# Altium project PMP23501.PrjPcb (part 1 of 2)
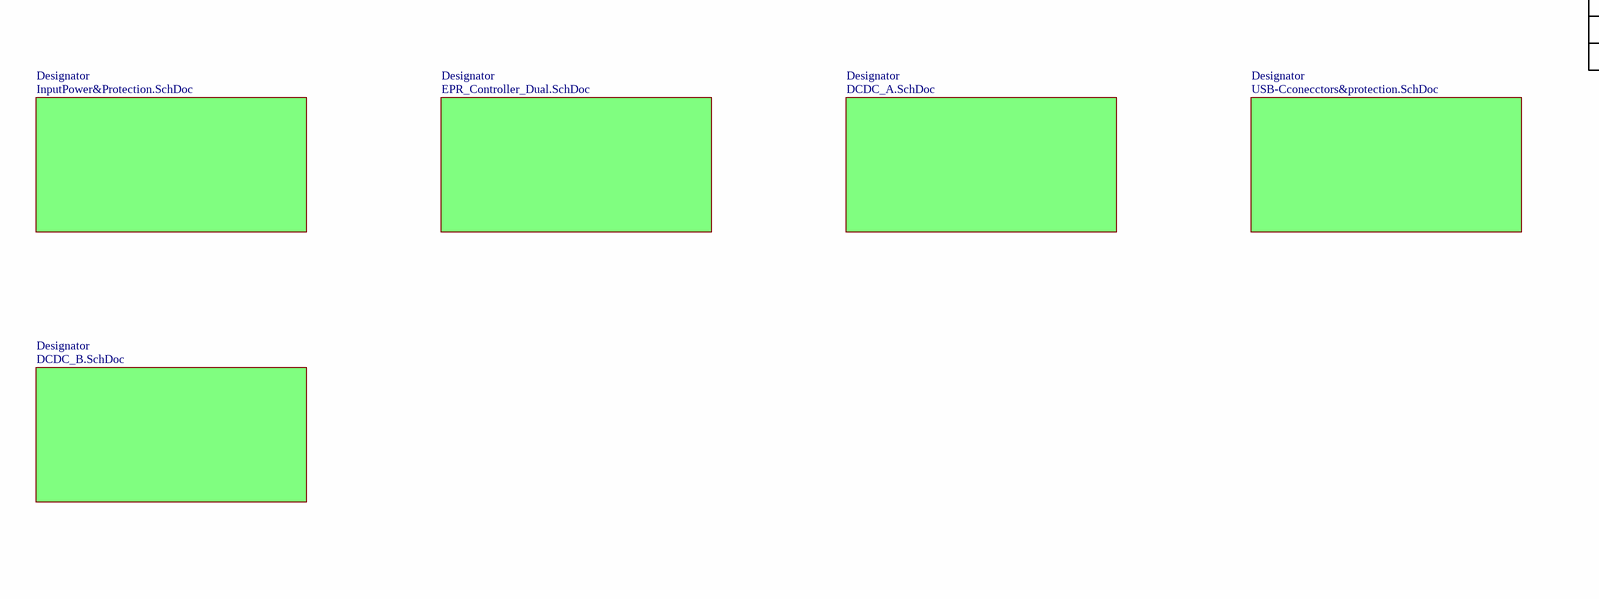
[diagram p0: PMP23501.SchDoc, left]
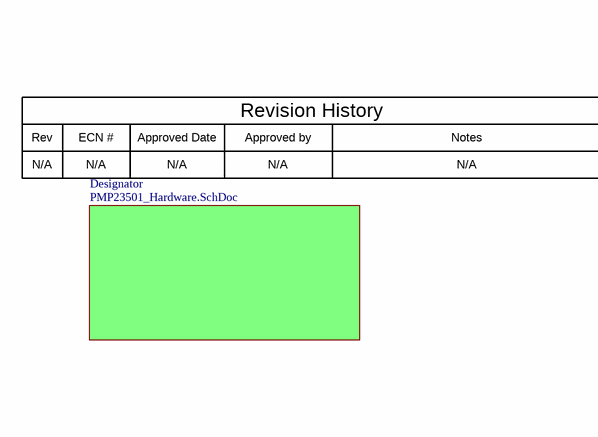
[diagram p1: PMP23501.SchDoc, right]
CopyrightYear: 2025; EVM_orderable: no; EVM_Orderable: no; PCB_Layout: Josh Mandelcorn; PCB_Rev: A; PRJ_Engineer: Josh Mandelcorn; PRJ_Number: PMP23501; PRJ_Title: Automotive 48Vin dual USB power; SCH_Rev: A; TechSupport: http://www.ti.com/support; TID: N/A
7 sheets, 185 parts. Net scope: flat (ports and power ports of the same name join across sheets).
Board file: PMP23501.PcbDoc
Sheets:
  PMP23501.SchDoc
    Designator = InputPower&Protection.SchDoc
    Designator = EPR_Controller_Dual.SchDoc
    Designator = DCDC_A.SchDoc
    Designator = USB-Cconecctors&protection.SchDoc
    Designator = PMP23501_Hardware.SchDoc
    Designator = DCDC_B.SchDoc

## Sheet PMP23501.SchDoc
size 431 x 279 mm; Date: Not shown in title block; ApprovedBy: Not shown in title block; CheckedBy: Not shown in title block; Author: Not shown in title block; CompanyName: Not shown in title block; Engineer: Not shown in title block; Organization: Not shown in title block; Address1: Not shown in title block; Address2: Not shown in title block; Address3: Not shown in title block; Address4: Not shown in title block; DocumentNumber: 1; Revision: Use project parameter SCH_Rev; SheetNumber: 1; SheetTotal: 7; PageSetup: Record=PageOptions¦CenterHorizontal=True¦CenterVertical=True¦PrintScale=1.00¦XCorrection=1.00¦YCorrection=1.00¦PrintKind=0¦BorderSize=5000000¦LeftOffset=0¦BottomOffset=0¦Orientation=2¦PaperLength=1000¦PaperWidth=1000¦Scale=100¦PaperSource=15¦PrintQuality=600¦MediaType=1¦DitherType=10¦PaperKind=Letter¦PrintScaleMode=1

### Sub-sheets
Designator = InputPower&Protection.SchDoc: no entries
Designator = EPR_Controller_Dual.SchDoc: no entries
Designator = DCDC_A.SchDoc: no entries
Designator = USB-Cconecctors&protection.SchDoc: no entries
Designator = PMP23501_Hardware.SchDoc: no entries
Designator = DCDC_B.SchDoc: no entries

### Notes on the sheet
- Rev
- N/A
- ECN #
- Approved Date
- Approved by
- Revision History
- Notes

## Sheet InputPower&Protection.SchDoc
size 431 x 279 mm; Date: Not shown in title block; ApprovedBy: Not shown in title block; CheckedBy: Not shown in title block; Author: Not shown in title block; CompanyName: Not shown in title block; Engineer: Not shown in title block; Organization: Not shown in title block; Address1: Not shown in title block; Address2: Not shown in title block; Address3: Not shown in title block; Address4: Not shown in title block; DocumentNumber: 2; Revision: Use project parameter SCH_Rev; SheetNumber: 2; SheetTotal: 7; PageSetup: Record=PageOptions¦CenterHorizontal=True¦CenterVertical=True¦PrintScale=1.00¦XCorrection=1.00¦YCorrection=1.00¦PrintKind=0¦BorderSize=5000000¦LeftOffset=0¦BottomOffset=0¦Orientation=2¦PaperLength=1000¦PaperWidth=1000¦Scale=100¦PaperSource=15¦PrintQuality=600¦MediaType=1¦DitherType=10¦PaperKind=Letter¦PrintScaleMode=1
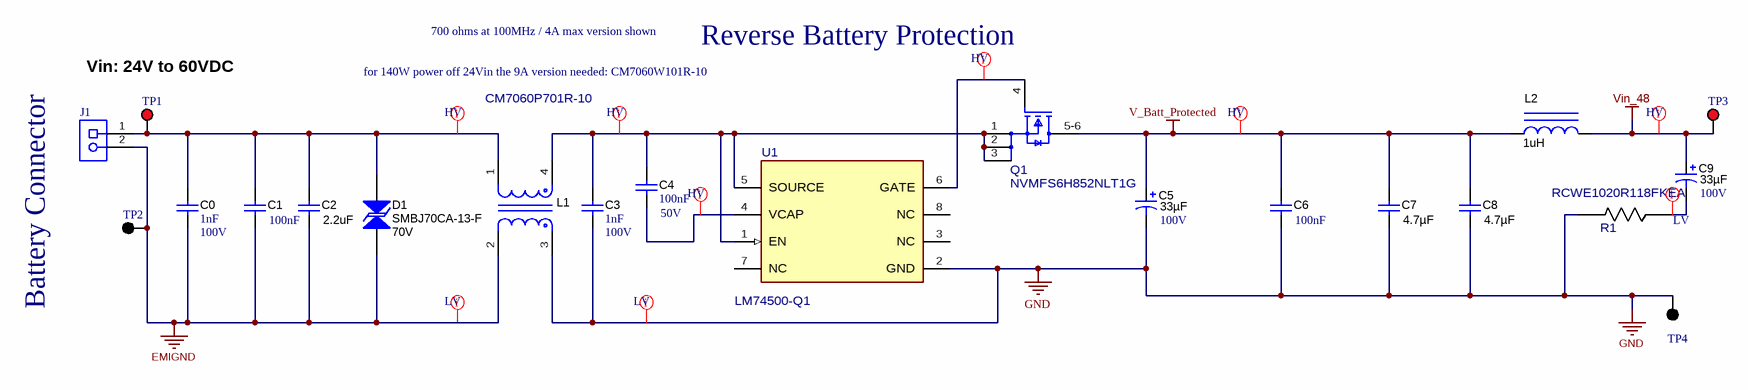
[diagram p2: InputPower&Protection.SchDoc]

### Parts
C0  Cap_F: 1nF  VDC_V: 100V  [0603]  (hidden comment: CGA3E2X7R2A102K080AA)
C1  Cap_F: 100nF  [0603L]  (hidden comment: GCJ188R72A104KA01D)
C2  ValueDisplayed: 2.2uF  [1206_180L]  (hidden comment: CGA5L3X7S2A225K160AB)
C3  Cap_F: 1nF  VDC_V: 100V  [0603]  (hidden comment: CGA3E2X7R2A102K080AA)
C4  Cap_F: 100nF  VDC_V: 50V  [0603]  (hidden comment: GCM188R71H104KA57D)
C5  Value2: 100V  ValueDisplayed: 33µF  [TG_V_1000x1020]  (hidden comment: EEE-TG2A330P)
C6  Cap_F: 100nF  [0603L]  (hidden comment: GCJ188R72A104KA01D)
C7  ValueDisplayed: 4.7µF  [1210_220L]  (hidden comment: GCM32DC72A475KE02L)
C8  ValueDisplayed: 4.7µF  [1210_220L]  (hidden comment: GCM32DC72A475KE02L)
C9  Value2: 100V  ValueDisplayed: 33µF  [TG_V_1000x1020]  (hidden comment: EEE-TG2A330P)
D1  SMBJ70CA-13-F  value 70V  [SMB-Bi]
J1  691253510002  [FP-691253510002_CONN_TERM_BLOCK2-MFG]  (value not drawn)
L1  CM7060P701R-10  [FP-CM7060P701R-10_SMT_CMC_7MM0_6MM0-MFG]
L2  ValueDisplayed: 1uH  [WE-MAPI_4020]  (hidden comment: 74438356010)
Q1  NVMFS6H852NLT1G  [FP-NVMFS6H852NLT1G_DFN5-MFG]
R1  RCWE1020R118FKEA  [FP-RCWE1020R118FKEA_1020-MFG]
TP1  5000  [Keystone5000]  (value not drawn)
TP2  5001  [Keystone5001]  (value not drawn)
TP3  5000  [Keystone5000]  (value not drawn)
TP4  5001  [Keystone5001]  (value not drawn)
U1  LM74500-Q1  [DDF0008A-MFG]

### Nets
EMIGND: C0.2 C1.2 C2.2 D1.1 J1.2 L1.2 TP2.1
GND: C3.2 C5.2(-) C6.2 C7.2 C8.2 L1.3 R1.2 TP4.1 U1.2(GND)
V_Batt_Protected: C5.1(+) C6.1 C7.1 C8.1 L2.1 Q1.5-6(D)
Vin_48: C9.1(+) L2.2 TP3.1
NetC0_1: C0.1 C1.1 C2.1 D1.2 J1.1 L1.1 TP1.1
NetC3_1: C3.1 C4.1 L1.4 Q1.1(S) Q1.2(S) Q1.3(S) U1.1(EN) U1.5(SOURCE)
NetC4_2: C4.2 U1.4(VCAP)
NetC9_2: C9.2(-) R1.1
NetQ1_4: Q1.4(G) U1.6(GATE)

Not connected (* = marked no-connect by the designer): U1 3(NC) 7(NC) 8(NC)

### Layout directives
net class LV; Parameter 1: ClassName: EMIGND, GND, NetC9_2
net class HV; Parameter 1: ClassName: NetC0_1, NetC3_1, NetC4_2, NetQ1_4, V_Batt_Protected, Vin_48

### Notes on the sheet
- Vin: 24V to 60VDC
- 700 ohms at 100MHz / 4A max version shown
- Reverse Battery Protection
- for 140W power off 24Vin the 9A version needed: CM7060W101R-10
- Battery Connector

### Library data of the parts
C0 C3 = CMP-0007081-4: CAP, CERM, 1000 pF, 100 V, +/- 10%, X7R, AEC-Q200 Grade 1, 0603; Manufacturer: TDK; TaMin_C: -55°C; ESR_ohm: 1.9714; Polarized: N; SizeAreaWB_mm2: 4.68; Value1: 1.97137 ohm; U/M: EA; Value: 1000pF; TaMax_C: 125°C; SizeZ_mm: 1; SizeX_mm: 1.6; SizeY_mm: 0.8; SizeArea_mm2: 1.28; AEC Qualified: Y; IRMS_A: 305.705mA; AEC Category: Q200
C1 C6 = CMP-0064935-4: CAP, CERM, 0.1 uF, 100 V,+/- 10%, X7R, AEC-Q200 Grade 1, 0603; Manufacturer: MuRata; TaMin_C: -55°C; Polarized: N; SizeAreaWB_mm2: 4.68; U/M: EA; Value: 0.1uF; TaMax_C: 125°C; SizeZ_mm: 1; SizeX_mm: 1.6; SizeY_mm: 0.8; Cap_Case: 0603; Value2: 100V; SizeArea_mm2: 1.28; AEC Qualified: Y; AEC Category: Q200; Value1: Unknown
C2 = CMP-0008790-2: CAP, CERM, 2.2 uF, 100 V, +/- 10%, X7S, AEC-Q200 Grade 1, 1206; Manufacturer: TDK; TaMin_C: -55°C; ESR_ohm: 5.718m; Polarized: N; SizeAreaWB_mm2: 10.92; Value1: 0.005718 ohm; U/M: EA; Value: 2.2uF; TaMax_C: 125°C; SizeZ_mm: 1.8; SizeX_mm: 3.2; SizeY_mm: 1.6; Cap_Case: 1206_180; Value2: 100V; SizeArea_mm2: 5.12; AEC Qualified: Y; Cap_F: 2.2µF; IRMS_A: 3.0363A; AEC Grade: 1; AEC Category: Q200
C4 = CMP-0007144-4: CAP, CERM, 0.1 uF, 50 V, +/- 10%, X7R, 0603; Manufacturer: MuRata; TaMin_C: -55°C; ESR_ohm: 0.02; Polarized: N; SizeAreaWB_mm2: 4.68; Value1: 0.02 ohm; U/M: EA; Value: 0.1uF; TaMax_C: 125°C; SizeZ_mm: 1; SizeX_mm: 1.6; SizeY_mm: 0.8; SizeArea_mm2: 1.28; IRMS_A: 1.84A; AEC Category: Q200
C5 C9 = CMP-0086185-1: CAP, AL, 33 µF, 100 V, +/- 20%, 1 ohm, AEC-Q200 Grade 1, SMD; Manufacturer: Panasonic; TaMin_C: -40°C; ESR_ohm: 1; Polarized: Y; SizeAreaWB_mm2: 151.29; Value1: 1 ohm; U/M: EA; Value: 33uF; TaMax_C: 125°C; SizeZ_mm: 10.5; SizeX_mm: 10.3; Cap_Case: 10x10.2mm; SizeArea_mm2: 106.09; CompType: Capacitor; AEC Category: Q200
C7 C8 = CMP-0082268-1: CAP, CERM, 4.7 µF, 100 V,+/- 10%, X7S, AEC-Q200 Grade 1, 1210; Manufacturer: MuRata; TaMin_C: -55°C; ESR_ohm: 1m; Polarized: N; SizeAreaWB_mm2: 14.7; Value1: 0.001 ohm; U/M: EA; Value: 4.7uF; TaMax_C: 125°C; SizeZ_mm: 2.2; SizeX_mm: 3.2; SizeY_mm: 2.5; Cap_Case: 1210; Value2: 100V; SizeArea_mm2: 8; AEC Qualified: Y; IRMS_A: 6A; AEC Grade: 1; AEC Category: Q200
D1 = CMP-0005587-3: Diode, TVS, Bi, 70 V, SMB; Manufacturer: Diodes Inc.; AEC Category: Q101; SizeX_mm: 5.6; SizeY_mm: 3.81; Ppk: 600W; SizeZ_mm: 2.6; SizeArea_mm2: 21.336; SizeAreaWB_mm2: 44.156
J1 = CMP-0095936-2: 2 Position Wire to Board Terminal Block Horizontal with Board 0.200" (5.08mm) Through Hole; Manufacturer: Wurth Electronics; Current_A: 16A; Max Wire Gauge: 12; Min Wire Gauge: 30; SizeZ_mm: 18.1mm; AEC Qualified: No; Is Female: yes; ContactFinish: Tin,Nickel; Voltage_V: 300V; Conn Gender: Female; Row_Count: 1
L1 = CMP-0094039-1: Common Mode Choke Power 700Ω 4A -40 to 125°C Wire Wound Surface Mount T/R; Manufacturer: Laird; AEC Qualified: No; DCR_ohm: 15m; SizeZ_mm: 3.8mm; Impedance At Frequency: 700Ω @ 100MHz
L2 = CMP-0064168-1: Inductor, Shielded, 1 uH, 7.2 A, 0.012 ohm, SMD; Manufacturer: Wurth Elektronik; Isat: 9A @ 20% inductance drop; Irms: 7.2A @ 40C rise; Green_Lifecycle: Active; SizeAreaWB_mm2: 26.01; DCR_ohm: 12m; Green_REACh: Passed; Value: 1uH; Imax_A: 7.2A; SizeZ_mm: 2.1; SizeX_mm: 4.1; SizeArea_mm2: 16.81; Ind_H: 1µH; AEC Qualified: N; AEC Category: Q200
Q1 = CMP-0122137-1: N-Channel 80 V 11A (Ta), 42A (Tc) 3.6W (Ta), 54W (Tc) Surface Mount 5-DFN (5x6) (8-SOFL); Manufacturer: onsemi; AEC Qualified: Yes; QgTyp_nC: 17nC @ 10V; Rdson45_ohm: 13.4m; SizeZ_mm: 1.1mm; VdsMax_V: 1.2V; Vgs_V: 20V; ChMode: False; AEC Grade: Grade 0; Drain To Source Breakdown Voltage: 80V; Input Capacitace At Vds: 906pF @ 40V; Number Of Channels: 1; Pulse Drain Current: 208A; Reverse Recovery Charge: 25nC; Reverse Recovery Time: 32ns; Rthja Max: 42°C/W; Standoff Height: 0mm; Threshold Vgs Max: 2V; TJmax_C: +175°C; Transconductance: 55S; Turn Off Delay Time: 18ns; Turn On Delay Time: 29ns; Typ Forward Diode Voltage: 0.81V
R1 = CMP-0087670-1: 118 mOhms ±1% 2W Chip Resistor Wide 2010 (5025 Metric), 1020 Automotive AEC-Q200, Current Sense, Moisture Resistant Thick Film; Manufacturer: Vishay; Res_ohm: 0.118; TempCo: 100ppm/°C; AEC Grade: Grade 0; AEC Qualified: Yes; Symbol Name: SYM-RCWE1020R118FKEA; SizeZ_mm: 0.7mm
TP1 TP3 = CMP-0055137-2: Test Point, Miniature, Red, TH; Manufacturer: Keystone Electronics; Green_REACh: Passed; CT: TRUE; ContactFinish: Silver; CNHeader: FALSE; Green_Lifecycle: Active
TP2 TP4 = CMP-0055138-2: Test Point, Miniature, Black, TH; Manufacturer: Keystone Electronics; ContactFinish: Silver; Green_Lifecycle: Active; Green_REACh: Passed; CT: TRUE; CNHeader: FALSE
U1 = CMP-0090679-1: Low IQ Reverse Battery Protection Controller; PartNumber: LM74500QDDFRQ1; Part Number: LM74500QDDFQ1; Manufacturer: Texas Instruments; TaMax_C: +125°C; Max Supply Voltage: 60V; TJmax_C: +150°C; AEC Qualified: Yes; AEC Grade: Grade 1; Min Supply Voltage: 4V; TaMin_C: -40°C; Nominal Supply Current: 80uA; Number Of Outputs: 1; Standoff Height: 0mm; SizeZ_mm: 1.1mm

## Sheet EPR_Controller_Dual.SchDoc
size 431 x 279 mm; Date: Not shown in title block; ApprovedBy: Not shown in title block; CheckedBy: Not shown in title block; Author: Not shown in title block; CompanyName: Not shown in title block; Engineer: Not shown in title block; Organization: Not shown in title block; Address1: Not shown in title block; Address2: Not shown in title block; Address3: Not shown in title block; Address4: Not shown in title block; DocumentNumber: 3; Revision: Use project parameter SCH_Rev; SheetNumber: 3; SheetTotal: 7; PageSetup: Record=PageOptions¦CenterHorizontal=True¦CenterVertical=True¦PrintScale=1.00¦XCorrection=1.00¦YCorrection=1.00¦PrintKind=0¦BorderSize=5000000¦LeftOffset=0¦BottomOffset=0¦Orientation=2¦PaperLength=1000¦PaperWidth=1000¦Scale=100¦PaperSource=15¦PrintQuality=600¦MediaType=1¦DitherType=10¦PaperKind=Letter¦PrintScaleMode=1
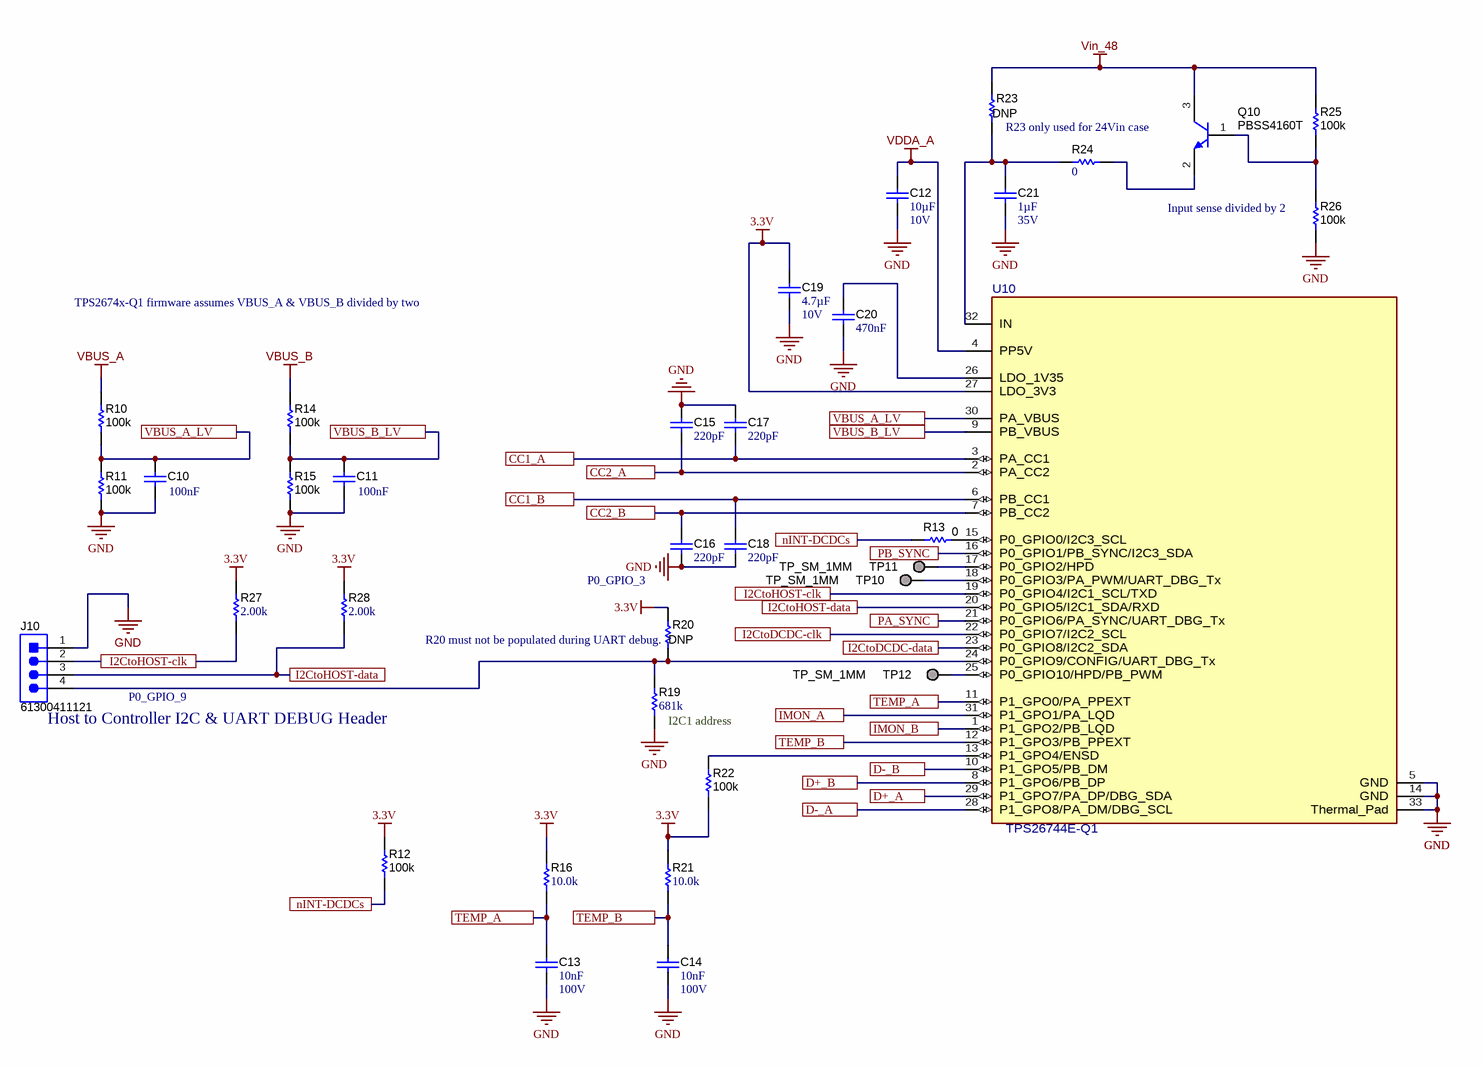
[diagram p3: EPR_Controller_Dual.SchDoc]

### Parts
C10  Cap_F: 100nF  [0603]  (hidden comment: GCJ188R72A104KA01D)
C11  Cap_F: 100nF  [0603]  (hidden comment: GCJ188R72A104KA01D)
C12  Cap_F: 10µF  VDC_V: 10V  [0805_HV]  (hidden comment: GCJ21BR71A106KE01L)
C13  Cap_F: 10nF  VDC_V: 100V  [0603]  (hidden comment: CGA3E2X7R2A103K080AA)
C14  Cap_F: 10nF  VDC_V: 100V  [0603]  (hidden comment: CGA3E2X7R2A103K080AA)
C15  Cap_F: 220pF  [0603]  (hidden comment: GRM188R72A221KA01D)
C16  Cap_F: 220pF  [0603]  (hidden comment: GRM188R72A221KA01D)
C17  Cap_F: 220pF  [0603]  (hidden comment: GRM188R72A221KA01D)
C18  Cap_F: 220pF  [0603]  (hidden comment: GRM188R72A221KA01D)
C19  Cap_F: 4.7µF  VDC_V: 10V  [0603]  (hidden comment: GRM188Z71A475ME15D)
C20  Cap_F: 470nF  [0603]  (hidden comment: GCM188R71E474KA64D)
C21  Cap_F: 1µF  VDC_V: 35V  [0603]  (hidden comment: CGA3E1X7R1V105K080AE)
J10  61300411121  [WURTH_61300411121]
Q10  PBSS4160T  [SOT-23]
R10  ValueDisplayed: 100k  [0603]  (hidden comment: CRCW0603100KFKEA)
R11  ValueDisplayed: 100k  [0603]  (hidden comment: CRCW0603100KFKEA)
R12  ValueDisplayed: 100k  [0603]  (hidden comment: CRCW0603100KFKEA)
R13  0  [0603]
R14  ValueDisplayed: 100k  [0603]  (hidden comment: CRCW0603100KFKEA)
R15  ValueDisplayed: 100k  [0603]  (hidden comment: CRCW0603100KFKEA)
R16  ValueDisplayed: 10.0k  [0603]  (hidden comment: CRCW060310K0FKEA)
R19  ValueDisplayed: 681k  [0603]  (hidden comment: CRCW0603681KFKEA)
R20  DNP  [0603]
R21  ValueDisplayed: 10.0k  [0603]  (hidden comment: CRCW060310K0FKEA)
R22  ValueDisplayed: 100k  [0603]  (hidden comment: CRCW0603100KFKEA)
R23  DNP  [0603]
R24  ValueDisplayed: 0  [0603]  (hidden comment: CRCW06030000Z0EA)
R25  ValueDisplayed: 100k  [0603]  (hidden comment: CRCW0603100KFKEA)
R26  ValueDisplayed: 100k  [0603]  (hidden comment: CRCW0603100KFKEA)
R27  ValueDisplayed: 2.00k  [0603]  (hidden comment: ERJ3EKF2001V)
R28  ValueDisplayed: 2.00k  [0603]  (hidden comment: ERJ3EKF2001V)
TP10  TP_SM_1MM  [TP_SM_1MM]  (no BOM)
TP11  TP_SM_1MM  [TP_SM_1MM]  (no BOM)
TP12  TP_SM_1MM  [TP_SM_1MM]  (no BOM)
U10  TPS26744E-Q1  [RHB0032AA-MFG]

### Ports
CC1_A, CC1_B, CC2_A, CC2_B, D+_A, D+_B, D-_A, D-_B, I2CtoDCDC-clk, I2CtoDCDC-data, I2CtoHOST-clk, I2CtoHOST-data, IMON_A, IMON_B, nINT-DCDCs, PA_SYNC, PB_SYNC, TEMP_A, TEMP_B, VBUS_A_LV, VBUS_B_LV

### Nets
3.3V: C19.2 R12.1 R16.2 R20.2 R21.2 R22.2 R27.2 R28.2 U10.27(LDO_3V3)
GND: C10.2 C11.2 C12.2 C13.2 C14.2 C15.1 C16.2 C17.1 C18.2 C19.1 C20.2 C21.1 J10.1 R11.2 R15.2 R19.1 R26.2 U10.5(GND) U10.14(GND) U10.33(Thermal_Pad)
VBUS_A: R10.1
VBUS_B: R14.1
VDDA_A: C12.1 U10.4(PP5V)
Vin_48: Q10.3(C) R23.2 R25.1
CC1_A: C17.2 U10.3(PA_CC1) ; port CC1_A
CC1_B: C18.1 U10.6(PB_CC1) ; port CC1_B
CC2_A: C15.2 U10.2(PA_CC2) ; port CC2_A
CC2_B: C16.1 U10.7(PB_CC2) ; port CC2_B
D+_A: U10.29(P1_GPO7/PA_DP/DBG_SDA) ; port D+_A
D+_B: U10.8(P1_GPO6/PB_DP) ; port D+_B
D-_A: U10.28(P1_GPO8/PA_DM/DBG_SCL) ; port D-_A
D-_B: U10.10(P1_GPO5/PB_DM) ; port D-_B
I2CtoDCDC-clk: U10.22(P0_GPIO7/I2C2_SCL) ; port I2CtoDCDC-clk
I2CtoDCDC-data: U10.23(P0_GPIO8/I2C2_SDA) ; port I2CtoDCDC-data
I2CtoHOST-clk: J10.2 R27.1 U10.19(P0_GPIO4/I2C1_SCL/TXD) ; port I2CtoHOST-clk
I2CtoHOST-data: J10.3 R28.1 U10.20(P0_GPIO5/I2C1_SDA/RXD) ; port I2CtoHOST-data
IMON_A: U10.31(P1_GPO1/PA_LQD) ; port IMON_A
IMON_B: U10.1(P1_GPO2/PB_LQD) ; port IMON_B
nINT-DCDCs: R12.2 R13.2 ; port nINT-DCDCs
PA_SYNC: U10.21(P0_GPIO6/PA_SYNC/UART_DBG_Tx) ; port PA_SYNC
PB_SYNC: U10.16(P0_GPIO1/PB_SYNC/I2C3_SDA) ; port PB_SYNC
TEMP_A: C13.1 R16.1 U10.11(P1_GPO0/PA_PPEXT) ; port TEMP_A
TEMP_B: C14.1 R21.1 U10.12(P1_GPO3/PB_PPEXT) ; port TEMP_B
VBUS_A_LV: C10.1 R10.2 R11.1 U10.30(PA_VBUS) ; port VBUS_A_LV
VBUS_B_LV: C11.1 R14.2 R15.1 U10.9(PB_VBUS) ; port VBUS_B_LV
NetC20_1: C20.1 U10.26(LDO_1V35)
NetC21_2: C21.2 R23.1 R24.2 U10.32(IN)
NetJ10_4: J10.4 R19.2 R20.1 U10.24(P0_GPIO9/CONFIG/UART_DBG_Tx)
NetQ10_1: Q10.1(B) R25.2 R26.1
NetQ10_2: Q10.2(E) R24.1
NetR13_1: R13.1 U10.15(P0_GPIO0/I2C3_SCL)
NetR22_1: R22.1 U10.13(P1_GPO4/ENSD)
NetTP10_1: TP10.1 U10.18(P0_GPIO3/PA_PWM/UART_DBG_Tx)
NetTP11_1: TP11.1 U10.17(P0_GPIO2/HPD)
NetTP12_1: TP12.1 U10.25(P0_GPIO10/HPD/PB_PWM)

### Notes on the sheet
- R23 only used for 24Vin case
- (near R26) Input sense divided by 2
- TPS2674x-Q1 firmware assumes VBUS_A & VBUS_B divided by two
- P0_GPIO_3
- P0_GPIO_9
- (near R20) R20 must not be populated during UART debug.
- (near J10) Host to Controller I2C & UART DEBUG Header
- (near R19) I2C1 address

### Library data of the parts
C10 C11 = CMP-0064935-4: CAP, CERM, 0.1 uF, 100 V,+/- 10%, X7R, AEC-Q200 Grade 1, 0603; Manufacturer: MuRata; TaMin_C: -55°C; Polarized: N; SizeAreaWB_mm2: 4.68; U/M: EA; Value: 0.1uF; TaMax_C: 125°C; SizeZ_mm: 1; SizeX_mm: 1.6; SizeY_mm: 0.8; Value2: 100V; SizeArea_mm2: 1.28; AEC Qualified: Y; AEC Category: Q200; Value1: Unknown
C12 = CMP-0079153-1: CAP, CERM, 10 µF, 10 V,+/- 10%, X7R, AEC-Q200 Grade 1, 0805; Manufacturer: MuRata; SizeAreaWB_mm2: 6.75; SizeArea_mm2: 2.5; AEC Qualified: Y; AEC Category: Q200; Value: 10uF; TaMax_C: 125°C; SizeZ_mm: 1.45; AEC Grade: 1; Polarized: N; TaMin_C: -55°C; SizeY_mm: 1.25; U/M: EA; SizeX_mm: 2; Cap_Case: 0805
C13 C14 = CMP-0007082-4: CAP, CERM, 0.01 uF, 100 V, +/- 10%, X7R, AEC-Q200 Grade 1, 0603; Manufacturer: TDK; TaMin_C: -55°C; ESR_ohm: 0.2354; Polarized: N; SizeAreaWB_mm2: 4.68; Value1: 0.235428 ohm; U/M: EA; Value: 0.01uF; TaMax_C: 125°C; SizeZ_mm: 1; SizeX_mm: 1.6; SizeY_mm: 0.8; SizeArea_mm2: 1.28; AEC Qualified: Y; IRMS_A: 396.995mA; AEC Category: Q200
C15-C18 = CMP-0007474-4: CAP, CERM, 220 pF, 100 V, +/- 10%, X7R, 0603; Manufacturer: MuRata; TaMin_C: -55°C; Polarized: N; SizeAreaWB_mm2: 4.68; Value1: Unknown; U/M: EA; Value: 220pF; TaMax_C: 125°C; SizeZ_mm: 1; SizeX_mm: 1.6; SizeY_mm: 0.8; Value2: 100V; SizeArea_mm2: 1.28; AEC Category: Q200
C19 = CMP-0007498-4: CAP, CERM, 4.7 uF, 10 V, +/- 20%, X7R, 0603; Manufacturer: MuRata; TaMin_C: -55°C; Polarized: N; SizeAreaWB_mm2: 4.68; Value1: Unknown; U/M: EA; Value: 4.7uF; TaMax_C: 125°C; SizeZ_mm: 1; SizeX_mm: 1.6; SizeY_mm: 0.8; SizeArea_mm2: 1.28; AEC Category: Q200
C20 = CMP-0007142-4: CAP, CERM, 0.47 uF, 25 V, +/- 10%, X7R, AEC-Q200 Grade 1, 0603; Manufacturer: MuRata; TaMin_C: -55°C; Polarized: N; SizeAreaWB_mm2: 4.68; Value1: Unknown; U/M: EA; Value: 0.47uF; TaMax_C: 125°C; SizeZ_mm: 1; SizeX_mm: 1.6; SizeY_mm: 0.8; Value2: 25V; SizeArea_mm2: 1.28; AEC Qualified: Y; AEC Category: Q200
C21 = CMP-0081259-1: CAP, CERM, 1 µF, 35 V,+/- 10%, X7R, AEC-Q200 Grade 1, 0603; Manufacturer: TDK; SizeAreaWB_mm2: 4.68; SizeArea_mm2: 1.28; AEC Qualified: Y; AEC Category: Q200; Value: 1uF; TaMax_C: 125°C; SizeZ_mm: 1; Polarized: N; TaMin_C: -55°C; SizeY_mm: 0.8; U/M: EA; SizeX_mm: 1.6
J10 = CMP-0054798-2: Header, 2.54 mm, 4x1, Gold, TH; Manufacturer: Wurth Elektronik; Pitch_mm: 2.54; Gender: Male; Row_Count: 1; Cert_UL: Y; Shrouded: N
Q10 = CMP-0000389-2: Transistor, NPN, 60 V, 0.9 A, SOT-23; Manufacturer: NXP Semiconductor; TaMax_C: 150°C; Value1: 0.9 A; Vcesat1_V: 90mV; SizeX_mm: 2.5; SizeY_mm: 3; TaMin_C: -65°C; IcRated_A: 900mA; CompType: BJT; SizeZ_mm: 1.1; Value: 60 V; SizeArea_mm2: 7.5; NPN: 1; Vceo_V: 60V; PNP: 0; AEC Category: Q101; SizeAreaWB_mm2: 14; U/M: EA
R10-R12 R14 R15 R22 R25 R26 = CMP-0021990-4: RES, 100 k, 1%, 0.1 W, AEC-Q200 Grade 0, 0603; Manufacturer: Vishay-Dale; Power_W: 100mW; TempCo: 100 ppm/C; Value: 100k; EIA_Code: E96; SizeX_mm: 1.6; SizeY_mm: 0.8; SizeZ_mm: 1; Value2: 0.1W; SizeArea_mm2: 1.28; AEC Qualified: Y; VDC_V: 75V; AEC Category: Q200; AEC Grade: 0
R13 = CMP-0025885-5: RES, 0, 5%, 0.1 W, 0603; Manufacturer: Yageo; PartNumber: RC0603JR-070RL; SizeZ_mm: 1; AEC Qualified: N; VDC_V: 75V; Power_W: 100mW; TempCo: 200 ppm/C; Value_Code: 0000; EIA_Code: E24; SizeX_mm: 1.6; SizeY_mm: 0.8; Value2: 0.1W; SizeArea_mm2: 1.28; AEC Category: Q200; SizeAreaWB_mm2: 4.68
R16 R21 = CMP-0021998-4: RES, 10.0 k, 1%, 0.1 W, AEC-Q200 Grade 0, 0603; Manufacturer: Vishay-Dale; Power_W: 100mW; TempCo: 100 ppm/C; Value_Code: 10k0; Value: 10.0k; EIA_Code: E96; Res_ohm: 10k; SizeX_mm: 1.6; SizeY_mm: 0.8; SizeZ_mm: 1; Value2: 0.1W; SizeArea_mm2: 1.28; AEC Qualified: Y; VDC_V: 75V; AEC Category: Q200; AEC Grade: 0
R19 = CMP-0022550-4: RES, 681 k, 1%, 0.1 W, AEC-Q200 Grade 0, 0603; Manufacturer: Vishay-Dale; Power_W: 100mW; TempCo: 100 ppm/C; Value: 681k; EIA_Code: E96; SizeX_mm: 1.6; SizeY_mm: 0.8; SizeZ_mm: 1; Value2: 0.1W; SizeArea_mm2: 1.28; AEC Qualified: Y; VDC_V: 75V; AEC Category: Q200; AEC Grade: 0
R20 R23 = CMP-0025885-5: RES, 0, 5%, 0.1 W, 0603; Manufacturer: Yageo; PartNumber: RC0603JR-070RL; Value: 0; SizeZ_mm: 1; AEC Qualified: N; VDC_V: 75V; Power_W: 100mW; TempCo: 200 ppm/C; Value_Code: 0000; EIA_Code: E24; SizeX_mm: 1.6; SizeY_mm: 0.8; Value2: 0.1W; SizeArea_mm2: 1.28; AEC Category: Q200; SizeAreaWB_mm2: 4.68
R24 = CMP-0025697-4: RES, 0, 5%, 0.1 W, AEC-Q200 Grade 0, 0603; Manufacturer: Vishay-Dale; Power_W: 100mW; TempCo: 200 ppm/C; Value_Code: 0000; Value: 0; EIA_Code: E24; SizeX_mm: 1.6; SizeY_mm: 0.8; SizeZ_mm: 1; Value2: 0.1W; SizeArea_mm2: 1.28; AEC Qualified: Y; VDC_V: 75V; AEC Category: Q200
R27 R28 = CMP-0078663-1: RES, 2.00 k, 1%, 0.1 W, AEC-Q200 Grade 0, 0603; Manufacturer: Panasonic; Power_W: 100mW; TempCo: 100 ppm/C; Value_Code: 2k00; Value: 2.00k; EIA_Code: E96; Res_ohm: 2k; SizeX_mm: 1.6; SizeY_mm: 0.8; SizeZ_mm: 1; Value2: 0.1W; SizeArea_mm2: 1.28; AEC Qualified: Y; AEC Grade: 0; AEC Category: Q200
TP10-TP12 = CMP-0003825-1: 1mm Test Point, SMT; Manufacturer: Any
U10 = CMP-0122052-1: Automotive Dual-Port USB Type-C® PD Controller with 240W EPR and DisplayPortTM over USB Type-C; Manufacturer: Texas Instruments; PartNumber: TPS26744EAATRHBRQ1; SizeZ_mm: 1mm; AEC Qualified: Yes; AEC Grade: Grade 2; Interface: I2C,UART,USB,LIN; Max Supply Voltage: 32V; Min Supply Voltage: 4.5V; Number Of Ports: 2; Standoff Height: 0mm; TaMax_C: +105°C; TaMin_C: -40°C; TJmax_C: +125°C

## Sheet DCDC_A.SchDoc: LM72880-Q1 EVM Schematic
size 431 x 279 mm; Date: Not shown in title block; ApprovedBy: Not shown in title block; CheckedBy: Not shown in title block; Author: Not shown in title block; CompanyName: Not shown in title block; DrawnBy: K Nielson; Engineer: E Lee; Organization: Not shown in title block; Address1: Not shown in title block; Address2: Not shown in title block; Address3: Not shown in title block; Address4: Not shown in title block; DocumentNumber: 4; Revision: Use project parameter SCH_Rev; SheetNumber: 4; SheetTotal: 7; PageSetup: Record=PageOptions¦CenterHorizontal=True¦CenterVertical=True¦PrintScale=1.00¦XCorrection=1.00¦YCorrection=1.00¦PrintKind=0¦BorderSize=5000000¦LeftOffset=0¦BottomOffset=0¦Orientation=2¦PaperLength=1000¦PaperWidth=1000¦Scale=100¦PaperSource=15¦PrintQuality=600¦MediaType=1¦DitherType=10¦PaperKind=Letter¦PrintScaleMode=1
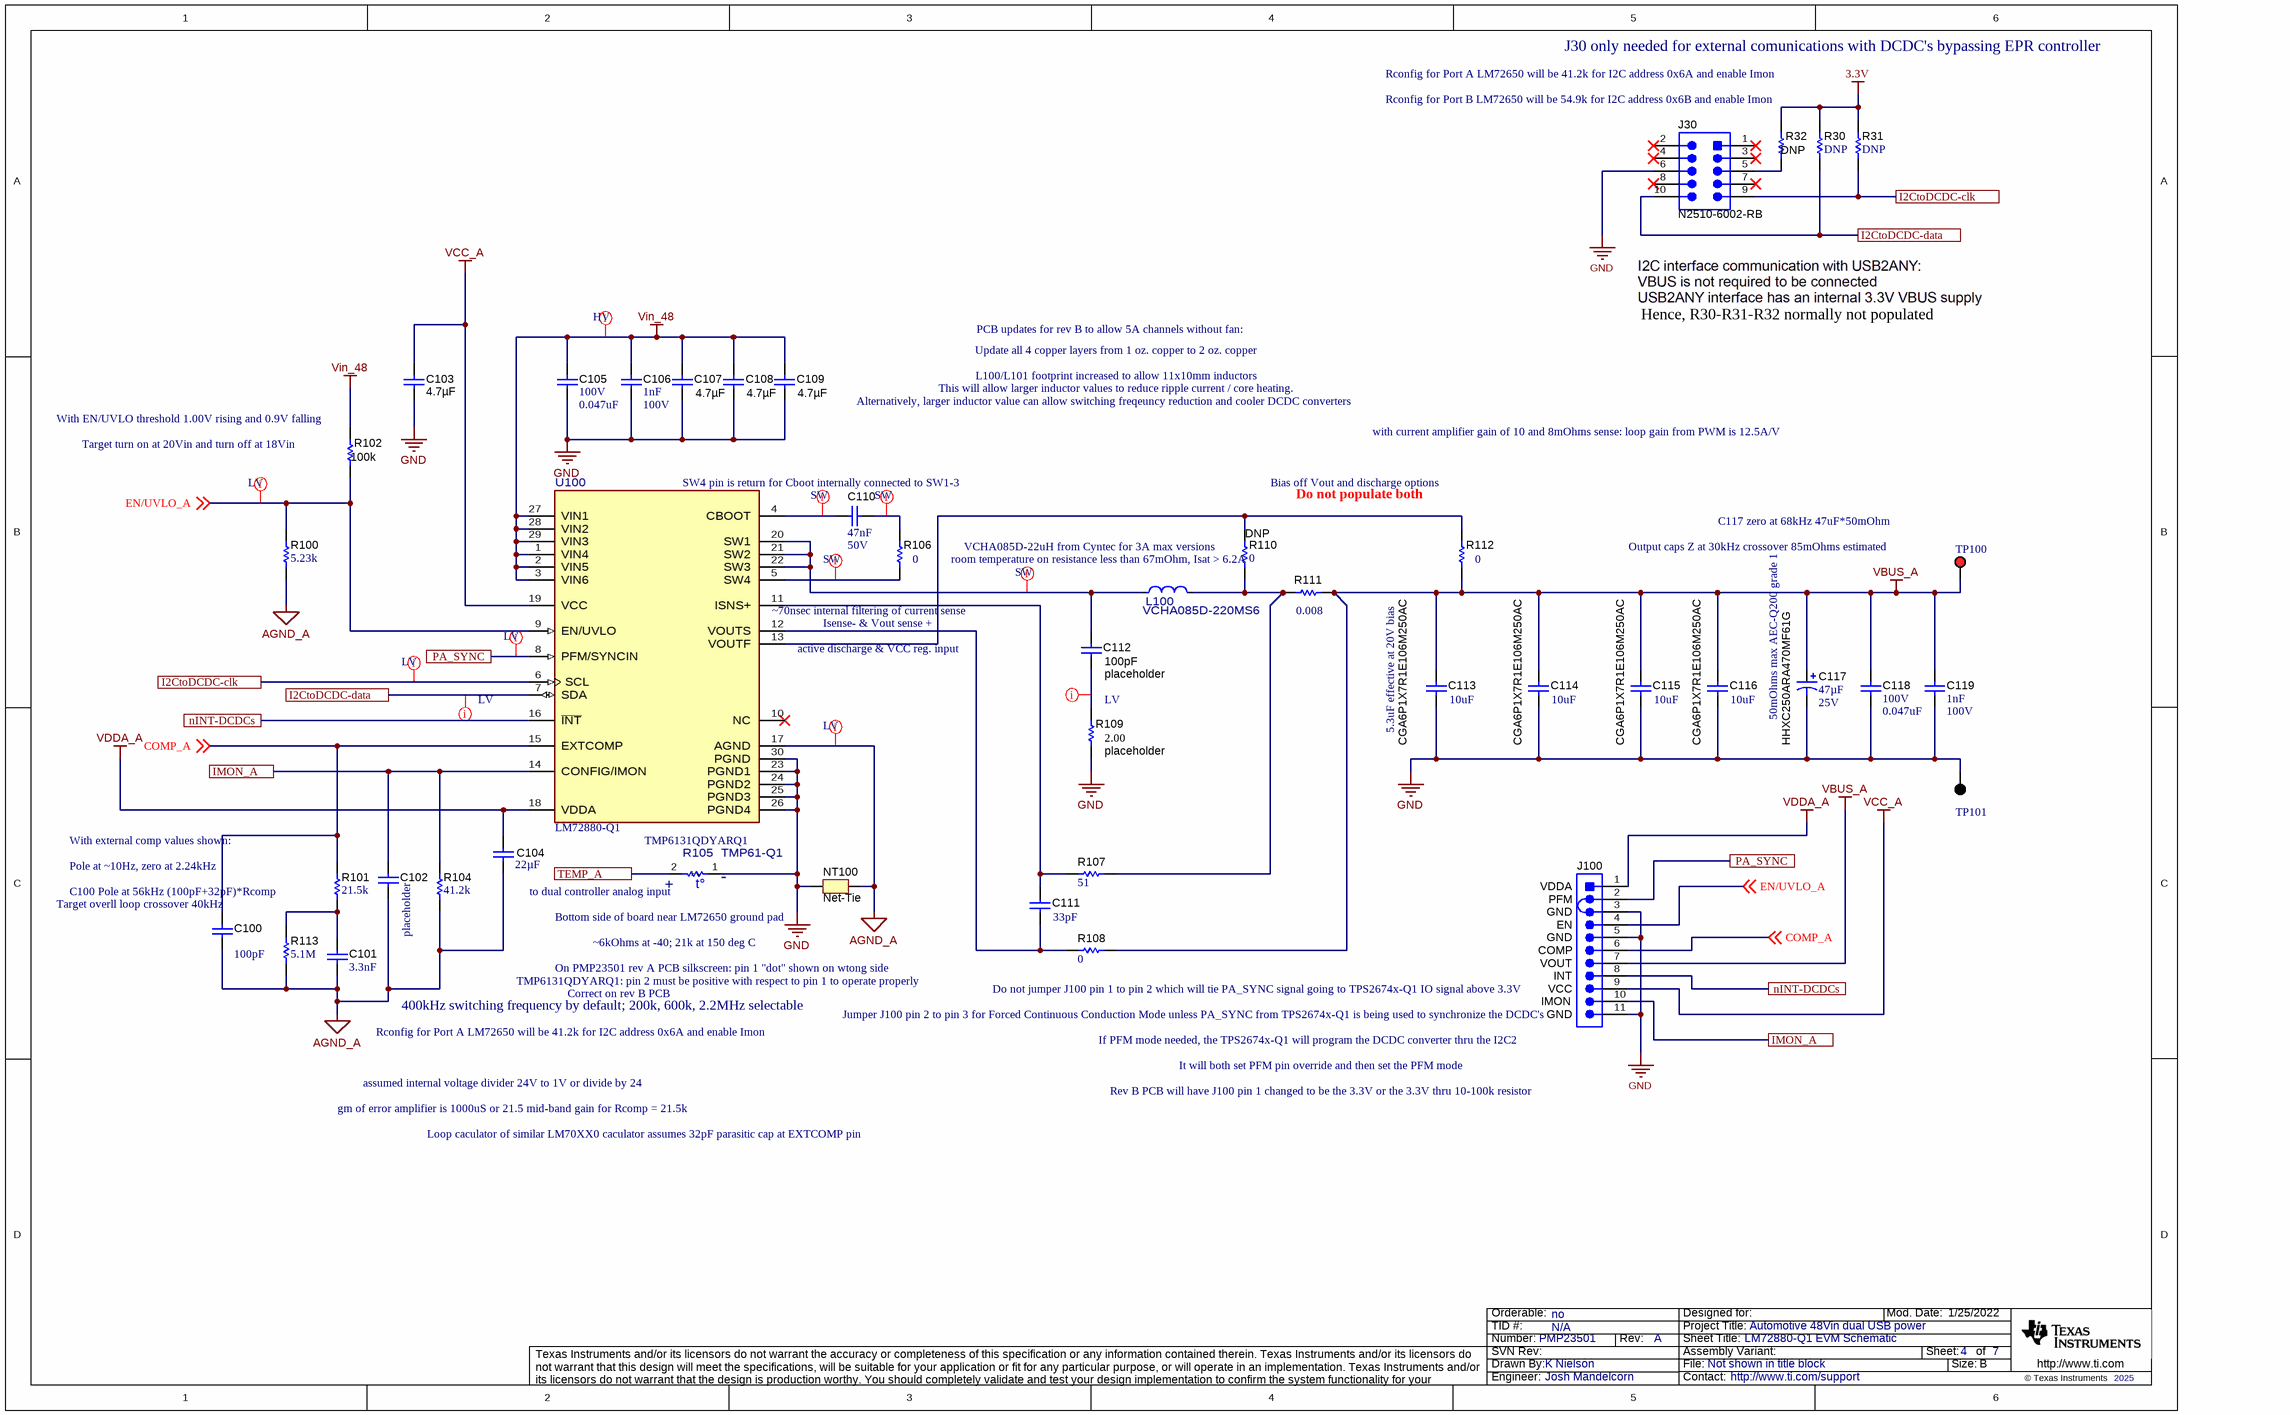
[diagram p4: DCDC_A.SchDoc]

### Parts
C100  ValueDisplayed: 100pF  [0603]  (hidden comment: GCM1885C2A101JA16D)
C101  Cap_F: 3.3nF  [0603]  (hidden comment: GCM188R72A332KA37D)
C102  ValueDisplayed: placeholder  [0603]  (hidden comment: GCM1885C2A100JA16D)
C103  Cap_F: 4.7µF  [0603]  (hidden comment: GRM188Z71A475ME15D)
C104  ValueDisplayed: 22µF  [0603]  (hidden comment: GRM188C80J226ME15D)
C105  VDC_V: 100V  ValueDisplayed: 0.047uF  [0603]  (hidden comment: CGA3E3X7S2A473K080AB)
C106  Cap_F: 1nF  VDC_V: 100V  [0603]  (hidden comment: CGA3E2X7R2A102K080AA)
C107  ValueDisplayed: 4.7µF  [1210_220]  (hidden comment: GCM32DC72A475KE02L)
C108  ValueDisplayed: 4.7µF  [1210_220]  (hidden comment: GCM32DC72A475KE02L)
C109  ValueDisplayed: 4.7µF  [1210_220]  (hidden comment: GCM32DC72A475KE02L)
C110  Cap_F: 47nF  VDC_V: 50V  [0603]  (hidden comment: CGA3E2X7R1H473K080AA)
C111  ValueDisplayed: 33pF  [0603]  (hidden comment: CGA3E2NP01H330J080AA)
C112  placeholder  ValueDisplayed: 100pF  [0603]
C113  CGA6P1X7R1E106M250AC  ValueDisplayed: 10uF  [1210_280]
C114  CGA6P1X7R1E106M250AC  ValueDisplayed: 10uF  [1210_280]
C115  CGA6P1X7R1E106M250AC  ValueDisplayed: 10uF  [1210_280]
C116  CGA6P1X7R1E106M250AC  ValueDisplayed: 10uF  [1210_280]
C117  HHXC250ARA470MF61G  ValueDisplayed: 47µF  VDC_V: 25V  [HXB_F61]
C118  VDC_V: 100V  ValueDisplayed: 0.047uF  [0603]  (hidden comment: CGA3E3X7S2A473K080AB)
C119  Cap_F: 1nF  VDC_V: 100V  [0603]  (hidden comment: CGA3E2X7R2A102K080AA)
J30  N2510-6002-RB  [CONN_2510-6002]
J100  TSW-111-07-G-S  [TSW-111-07-G-S]  (value not drawn)
L100  VCHA085D-220MS6  [FP-VCHA075D-8R2MS6_SMD-MFG]
NT100  Net-Tie  [Net-Tie_10mil]  (net tie, no BOM)
R30  DNP  [0603]
R31  ValueDisplayed: DNP  [0603]  (hidden comment: ERJ3EKF2001V)
R32  DNP  [0603]
R100  ValueDisplayed: 5.23k  [0603]  (hidden comment: CRCW06035K23FKEA)
R101  ValueDisplayed: 21.5k  [0603]  (hidden comment: CRCW060321K5FKEA)
R102  ValueDisplayed: 100k  [0603]  (hidden comment: CRCW0603100KFKEA)
R104  ValueDisplayed: 41.2k  [0603]  (hidden comment: CRCW060341K2FKEA)
R105  TMP61-Q1  PartNumber: TMP6131QDYARQ1  [DYA0002A-MFG]
R106  value 0  [0603]  (hidden comment: RC0603JR-070RL)
R107  ValueDisplayed: 51  [0603]  (hidden comment: CRCW060351R0JNEA)
R108  value 0  [0603]  (hidden comment: RC0603JR-070RL)
R109  placeholder  ValueDisplayed: 2.00  [0603]
R110  DNP  value 0  [0603]
R111  ValueDisplayed: 0.008  [KRL2012]  (hidden comment: KRL2012M-R008-F-T1)
R112  value 0  [0603]  (hidden comment: RC0603JR-070RL)
R113  ValueDisplayed: 5.1M  [0603]  (hidden comment: CRCW06035M10JNEA)
TP100  5000  [Keystone5000]  (value not drawn)
TP101  5001  [Keystone5001]  (value not drawn)
U100  LM72880-Q1  [RRX0029B-MFG]

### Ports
I2CtoDCDC-clk, I2CtoDCDC-data, IMON_A, nINT-DCDCs, PA_SYNC, TEMP_A

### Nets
3.3V: R30.2 R31.2 R32.2
AGND_A: C100.2 C101.2 C102.2 C104.1 NT100.2 R100.1 R104.1 R113.1 U100.17(AGND)
GND: C103.2 C105.2 C106.2 C107.2 C108.2 C109.2 C113.2 C114.2 C115.2 C116.2 C117.2(-) C118.2 C119.2 J30.6 J100.3 J100.5 J100.11 NT100.1 R105.1(-) R109.2 TP101.1 U100.23(PGND1) U100.24(PGND2) U100.25(PGND3) U100.26(PGND4) U100.30(PGND)
VBUS_A: C113.1 C114.1 C115.1 C116.1 C117.1(+) C118.1 C119.1 J100.7 R108.2 R111.2 R112.2 TP100.1
VCC_A: C103.1 J100.9 U100.19(VCC)
VDDA_A: C104.2 J100.1 U100.18(VDDA)
Vin_48: C105.1 C106.1 C107.1 C108.1 C109.1 R102.2 U100.1(VIN4) U100.2(VIN5) U100.3(VIN6) U100.27(VIN1) U100.28(VIN2) U100.29(VIN3)
COMP_A: C100.1 J100.6 R101.2 U100.15(EXTCOMP) ; off-sheet COMP_A
EN/UVLO_A: J100.4 R100.2 R102.1 U100.9(EN/UVLO) ; off-sheet EN/UVLO_A
I2CtoDCDC-clk: J30.9 R31.1 U100.6(SCL) ; port I2CtoDCDC-clk
I2CtoDCDC-data: J30.10 R30.1 U100.7(SDA) ; port I2CtoDCDC-data
IMON_A: C102.1 J100.10 R104.2 U100.14(CONFIG/IMON) ; port IMON_A
nINT-DCDCs: J100.8 U100.16(~{INT}) ; port nINT-DCDCs
PA_SYNC: J100.2 U100.8(PFM/SYNCIN) ; port PA_SYNC
TEMP_A: R105.2(+) ; port TEMP_A
NetC101_1: C101.1 R101.1 R113.2
NetC110_1: C110.1 R106.1
NetC110_2: C110.2 U100.4(CBOOT)
NetC111_1: C111.1 R107.1 U100.11(ISNS+)
NetC111_2: C111.2 R108.1 U100.12(VOUTS)
NetC112_1: C112.1 L100.1 U100.20(SW1) U100.21(SW2) U100.22(SW3)
NetC112_2: C112.2 R109.1
NetJ30_5: J30.5 R32.1
NetL100_2: L100.2 R107.2 R110.1 R111.1
NetR106_2: R106.2 U100.5(SW4)
NetR110_2: R110.2 R112.1 U100.13(VOUTF)

Not connected (* = marked no-connect by the designer): J30 1* 2* 3* 4* 7* 8*; U100 10(NC)*

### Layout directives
net class HV; Parameter 1: ClassName: Vin_48
net class LV; Parameter 1: ClassName: AGND_A, EN/UVLO_A, I2CtoDCDC-clk, I2CtoDCDC-data, NetC112_2, PA_SYNC
net class SW; Parameter 1: ClassName: NetC110_1, NetC110_2, NetC112_1, NetR106_2

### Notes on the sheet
- Rconfig for Port A LM72650 will be 41.2k for I2C address 0x6A and enable Imon
- J30 only needed for external comunications with DCDC's bypassing EPR controller
- Rconfig for Port B LM72650 will be 54.9k for I2C address 0x6B and enable Imon
- PCB updates for rev B to allow 5A channels without fan:
- Update all 4 copper layers from 1 oz. copper to 2 oz. copper
- Hence, R30-R31-R32 normally not populated
- (near C109) Alternatively, larger inductor value can allow switching freqeuncy reduction and cooler DCDC converters
- L100/L101 footprint increased to allow 11x10mm inductors
- This will allow larger inductor values to reduce ripple current / core heating.
- (near R102) With EN/UVLO threshold 1.00V rising and 0.9V falling
- (near R102) Target turn on at 20Vin and turn off at 18Vin
- with current amplifier gain of 10 and 8mOhms sense: loop gain from PWM is 12.5A/V
- SW4 pin is return for Cboot internally connected to SW1-3
- Bias off Vout and discharge options
- Do not populate both
- C117 zero at 68kHz 47uF*50mOhm
- (near R110) room temperature on resistance less than 67mOhm, Isat > 6.2A
- (near R110) VCHA085D-22uH from Cyntec for 3A max versions
- (near TP100) Output caps Z at 30kHz crossover 85mOhms estimated
- (near U100) ~70nsec internal filtering of current sense
- (near U100) active discharge & VCC reg. input
- Isense- & Vout sense +
- (near C113) 5.3uF effective at 20V bias
- (near C117) 50mOhms max AEC-Q200 grade 1
- With external comp values shown:
- (near C100) Target overll loop crossover 40kHz
- Pole at
  0Hz, zero at 2.24kHz
- C100 Pole at 56kHz (100pF+32pF)*Rcomp
- (near R105) to dual controller analog input
- Bottom side of board near LM72650 ground pad
- (near R105) +
- (near R105) -
- (near J100) VDDA
- (near J100) GND
- (near J100) PFM
- (near J100) EN
- TMP6131QDYARQ1: pin 2 must be positive with respect to pin 1 to operate properly
- On PMP23501 rev A PCB silkscreen: pin 1 "dot" shown on wtong side
- ~6kOhms at -40; 21k at 150 deg C
- Do not jumper J100 pin 1 to pin 2 which will tie PA_SYNC signal going to TPS2674x-Q1 IO signal above 3.3V
- (near J100) COMP
- (near J100) VOUT
- (near J100) VCC
- (near J100) INT
- 400kHz switching frequency by default; 200k, 600k, 2.2MHz selectable
- Correct on rev B PCB
- (near J100) Jumper J100 pin 2 to pin 3 for Forced Continuous Conduction Mode unless PA_SYNC from TPS2674x-Q1 is being used to synchronize the DCDC's
- If PFM mode needed, the TPS2674x-Q1 will program the DCDC converter thru the I2C2
- (near J100) IMON
- gm of error amplifier is 1000uS or 21.5 mid-band gain for Rcomp = 21.5k
- assumed internal voltage divider 24V to 1V or divide by 24
- It will both set PFM pin override and then set the PFM mode
- Rev B PCB will have J100 pin 1 changed to be the 3.3V or the 3.3V thru 10-100k resistor
- Loop caculator of similar LM70XX0 caculator assumes 32pF parasitic cap at EXTCOMP pin

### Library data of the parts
C100 = CMP-0007130-4: CAP, CERM, 100 pF, 100 V, +/- 5%, C0G/NP0, AEC-Q200 Grade 1, 0603; Manufacturer: MuRata; TaMin_C: -55°C; Polarized: N; SizeAreaWB_mm2: 4.68; Value1: Unknown; U/M: EA; TaMax_C: 125°C; SizeZ_mm: 1; SizeX_mm: 1.6; SizeY_mm: 0.8; Value2: 100V; SizeArea_mm2: 1.28; AEC Qualified: Y; AEC Category: Q200; Value: 100pF
C101 = CMP-0007148-4: CAP, CERM, 3300 pF, 100 V, +/- 10%, X7R, AEC-Q200 Grade 1, 0603; Manufacturer: MuRata; TaMin_C: -55°C; Polarized: N; SizeAreaWB_mm2: 4.68; Value1: Unknown; U/M: EA; Value: 3300pF; TaMax_C: 125°C; SizeZ_mm: 1; SizeX_mm: 1.6; SizeY_mm: 0.8; Value2: 100V; SizeArea_mm2: 1.28; AEC Qualified: Y; AEC Category: Q200
C102 = CMP-0084283-1: CAP, CERM, 10 pF, 100 V,+/- 5%, C0G/NP0, AEC-Q200 Grade 1, 0603; Manufacturer: MuRata; TaMax_C: 125°C; Cap_F: 10pF; Value2: 100V; SizeX_mm: 1.6; SizeY_mm: 0.8; SizeArea_mm2: 1.28; Polarized: N; AEC Category: Q200; SizeAreaWB_mm2: 4.68; AEC Qualified: Y; SizeZ_mm: 1; Value: 10pF; U/M: EA; TaMin_C: -55°C
C103 = CMP-0007498-4: CAP, CERM, 4.7 uF, 10 V, +/- 20%, X7R, 0603; Manufacturer: MuRata; Polarized: N; Value: 4.7uF; U/M: EA; Value1: Unknown; VDC_V: 10V; TaMin_C: -55°C; TaMax_C: 125°C; AEC Category: Q200; SizeArea_mm2: 1.28; SizeAreaWB_mm2: 4.68; SizeX_mm: 1.6; SizeY_mm: 0.8; SizeZ_mm: 1
C104 = CMP-0079996-1: CAP, CERM, 22 µF, 6.3 V,+/- 20%, X6S, 0603; Manufacturer: MuRata; Polarized: N; Value: 22uF; U/M: EA; VDC_V: 6.3V; TaMin_C: -55°C; TaMax_C: 105°C; AEC Category: Q200; SizeArea_mm2: 1.28; SizeAreaWB_mm2: 4.68; SizeX_mm: 1.6; SizeY_mm: 0.8; SizeZ_mm: 1
C105 C118 = CMP-0007101-4: CAP, CERM, 0.047 uF, 100 V, +/- 10%, X7S, AEC-Q200 Grade 1, 0603; Manufacturer: TDK; TaMin_C: -55°C; ESR_ohm: 89.796m; Polarized: N; SizeAreaWB_mm2: 4.68; Value1: 0.089796 ohm; U/M: EA; TaMax_C: 125°C; SizeZ_mm: 1; SizeX_mm: 1.6; SizeY_mm: 0.8; SizeArea_mm2: 1.28; AEC Qualified: Y; Cap_F: 47nF; IRMS_A: 567.484mA; AEC Category: Q200
C106 C119 = CMP-0007081-4: as C0 on sheet InputPower&Protection
C107-C109 = CMP-0082268-1: as C7 on sheet InputPower&Protection
C110 = CMP-0007079-4: CAP, CERM, 0.047 uF, 50 V, +/- 10%, X7R, AEC-Q200 Grade 1, 0603; Manufacturer: TDK; TaMin_C: -55°C; ESR_ohm: 49.007m; Polarized: N; SizeAreaWB_mm2: 4.68; Value1: 0.049007 ohm; U/M: EA; TaMax_C: 125°C; SizeZ_mm: 1; SizeX_mm: 1.6; SizeY_mm: 0.8; SizeArea_mm2: 1.28; AEC Qualified: Y; IRMS_A: 767.528mA; AEC Category: Q200
C111 = CMP-0007076-4: CAP, CERM, 33 pF, 50 V, +/- 5%, C0G/NP0, AEC-Q200 Grade 0, 0603; Manufacturer: TDK; TaMin_C: -55°C; Polarized: N; SizeAreaWB_mm2: 4.68; Value1: Unknown; U/M: EA; Value: 33pF; TaMax_C: 150°C; SizeZ_mm: 1; SizeX_mm: 1.6; SizeY_mm: 0.8; Value2: 50V; SizeArea_mm2: 1.28; AEC Qualified: Y; AEC Grade: 0; AEC Category: Q200
C112 = CMP-0007237-4: CAP, CERM, 100 pF, 100 V, +/- 5%, C0G/NP0, 0603; Manufacturer: MuRata; PartNumber: GRM1885C2A101JA01D; TaMin_C: -55°C; Polarized: N; SizeAreaWB_mm2: 4.68; Value1: Unknown; U/M: EA; Value: 100pF; TaMax_C: 125°C; SizeZ_mm: 1; SizeX_mm: 1.6; SizeY_mm: 0.8; Value2: 100V; SizeArea_mm2: 1.28; AEC Category: Q200
C113-C116 = CMP-0009155-2: CAP, CERM, 10 uF, 25 V, +/- 20%, X7R, AEC-Q200 Grade 1, 1210; Manufacturer: TDK; TaMin_C: -55°C; Polarized: N; SizeAreaWB_mm2: 14.7; Value1: Unknown; U/M: EA; Value: 10uF; TaMax_C: 125°C; SizeZ_mm: 2.8; SizeX_mm: 3.2; SizeY_mm: 2.5; Cap_Case: 1210; Value2: 25V; SizeArea_mm2: 8; AEC Qualified: Y; Cap_F: 10µF; AEC Grade: 1; AEC Category: Q200
C117 = CMP-0750159-1: CAP, AL, 47 µF, 25 V, +/- 20%, 0.05 ohm, AEC-Q200 Grade 1, SMD; Manufacturer: Chemi-Con; TaMin_C: -55°C; Cap_Case: 6.3x5.8mm; CompType: Capacitor; TaMax_C: 125°C; U/M: EA; Value: 47uF; AEC Grade: 1; AEC Category: Q200; AEC Qualified: Y; ESR_ohm: 50m
J30 = CMP-0055448-2: Header (shrouded), 100mil, 5x2, High-Temperature, Gold, TH; Manufacturer: 3M; Green_Lifecycle: Active; Green_REACh: Passed
J100 = CMP-0075454-1: Header, 100mil, 11x1, Gold, TH; Manufacturer: Samtec; Pitch_mm: 2.54; Cert_VDE: N; Gender: Male; Cert_CSA: Y; Voltage_V: 550V; Green_REACh: Passed; Current_A: 6.3A; CT: False; Green_Lifecycle: Active; Row_Count: 1; CNHeader: True
L100 = CMP-0089036-1: Power Choke Coil; PartNumber: VCHA075D-8R2MS6; Manufacturer: Cyntec; DCR_ohm: 31.9m; AEC Grade: Grade 0; Ind_H: 8.2µH; Material: Metal dust; Isat: 9A; Irms: 5.6A; AEC Qualified: Yes; SizeZ_mm: 5.4mm
NT100 = CMP-0078142-6: Single point connection between nets.
R30 = CMP-0078663-1: RES, 2.00 k, 1%, 0.1 W, AEC-Q200 Grade 0, 0603; Manufacturer: Panasonic; PartNumber: ERJ3EKF2001V; Power_W: 100mW; TempCo: 100 ppm/C; Value_Code: 2k00; Value: 2.00k; EIA_Code: E96; Res_ohm: 2k; SizeX_mm: 1.6; SizeY_mm: 0.8; SizeZ_mm: 1; Value2: 0.1W; SizeArea_mm2: 1.28; AEC Qualified: Y; AEC Grade: 0; AEC Category: Q200
R31 = CMP-0078663-1: as R27 on sheet EPR_Controller_Dual
R32 = CMP-0025885-5: as R20 on sheet EPR_Controller_Dual
R100 = CMP-0022510-4: RES, 5.23 k, 1%, 0.1 W, AEC-Q200 Grade 0, 0603; Manufacturer: Vishay-Dale; Power_W: 100mW; TempCo: 100 ppm/C; Value_Code: 5k23; Value: 5.23k; EIA_Code: E96; SizeX_mm: 1.6; SizeY_mm: 0.8; SizeZ_mm: 1; Value2: 0.1W; SizeArea_mm2: 1.28; AEC Qualified: Y; VDC_V: 75V; AEC Category: Q200; AEC Grade: 0
R101 = CMP-0022213-4: RES, 21.5 k, 1%, 0.1 W, AEC-Q200 Grade 0, 0603; Manufacturer: Vishay-Dale; Power_W: 100mW; TempCo: 100 ppm/C; Value_Code: 21k5; Value: 21.5k; EIA_Code: E96; SizeX_mm: 1.6; SizeY_mm: 0.8; SizeZ_mm: 1; Value2: 0.1W; SizeArea_mm2: 1.28; AEC Qualified: Y; VDC_V: 75V; AEC Category: Q200; AEC Grade: 0
R102 = CMP-0021990-4: as R10 on sheet EPR_Controller_Dual
R104 = CMP-0022414-4: RES, 41.2 k, 1%, 0.1 W, AEC-Q200 Grade 0, 0603; Manufacturer: Vishay-Dale; Power_W: 100mW; TempCo: 100 ppm/C; Value_Code: 41k2; Value: 41.2k; EIA_Code: E96; SizeX_mm: 1.6; SizeY_mm: 0.8; SizeZ_mm: 1; Value2: 0.1W; SizeArea_mm2: 1.28; AEC Qualified: Y; VDC_V: 75V; AEC Category: Q200; AEC Grade: 0
R105 = CMP-0123120-1: Automotive ±1% tolerance 10kΩ linear thermistor available in an 0402 package option 2-SOT-5X3 -40 to 150; Manufacturer: Texas Instruments; SizeZ_mm: 0.77mm; AEC Grade: Grade 0; AEC Qualified: Yes; Max Current: 400uA; TaMax_C: +150°C; TaMin_C: -40°C; TempCo: 6400ppm/°C; TJmax_C: +155°C; VDC_V: 5.5V
R106 R108 R112 = CMP-0025885-5: RES, 0, 5%, 0.1 W, 0603; Manufacturer: Yageo; SizeZ_mm: 1; AEC Qualified: N; VDC_V: 75V; Power_W: 100mW; TempCo: 200 ppm/C; Value_Code: 0000; EIA_Code: E24; SizeX_mm: 1.6; SizeY_mm: 0.8; Value2: 0.1W; SizeArea_mm2: 1.28; AEC Category: Q200; SizeAreaWB_mm2: 4.68
R107 = CMP-0025825-4: RES, 51, 5%, 0.1 W, AEC-Q200 Grade 0, 0603; Manufacturer: Vishay-Dale; Power_W: 100mW; TempCo: 200 ppm/C; Value_Code: 51R0; Value: 51; EIA_Code: E24; SizeX_mm: 1.6; SizeY_mm: 0.8; SizeZ_mm: 1; Value2: 0.1W; SizeArea_mm2: 1.28; AEC Qualified: Y; VDC_V: 75V; AEC Category: Q200; AEC Grade: 0
R109 = CMP-0022302-4: RES, 2.00, 1%, 0.1 W, AEC-Q200 Grade 0, 0603; Manufacturer: Vishay-Dale; PartNumber: CRCW06032R00FKEA; Power_W: 100mW; TempCo: 100 ppm/C; Value_Code: 2R00; Value: 2.00; EIA_Code: E96; Res_ohm: 2; SizeX_mm: 1.6; SizeY_mm: 0.8; SizeZ_mm: 1; Value2: 0.1W; SizeArea_mm2: 1.28; AEC Qualified: Y; VDC_V: 75V; AEC Category: Q200; AEC Grade: 0
R110 = CMP-0025885-5: as R13 on sheet EPR_Controller_Dual
R111 = CMP-0015103-2: RES, 0.008, 1%, 1 W, AEC-Q200 Grade 0, 0508; Manufacturer: Susumu Co Ltd; Value: 0.008; Res_ohm: 8m; AEC Grade: 0; Power_W: 1W; TempCo: 25 ppm/C; AEC Qualified: Y; Value_Code: 8L000; U/M: EA; EIA_Code: E96; AEC Category: Q200
R113 = CMP-0025832-4: RES, 5.1 M, 5%, 0.1 W, AEC-Q200 Grade 0, 0603; Manufacturer: Vishay-Dale; Power_W: 100mW; TempCo: 200 ppm/C; Value_Code: 5M10; Value: 5.1Meg; EIA_Code: E24; SizeX_mm: 1.6; SizeY_mm: 0.8; SizeZ_mm: 1; Value2: 0.1W; SizeArea_mm2: 1.28; AEC Qualified: Y; VDC_V: 75V; AEC Category: Q200; AEC Grade: 0
TP100 = CMP-0055137-2: as TP1 on sheet InputPower&Protection
TP101 = CMP-0055138-2: as TP2 on sheet InputPower&Protection
U100 = CMP-0123475-2: Manufacturer: Texas Instruments; SizeZ_mm: 1mm; AEC Qualified: No; Standoff Height: 0mm; AEC Category: Q200; CompType: IC

## Sheet USB-Cconecctors&protection.SchDoc
size 431 x 279 mm; Date: Not shown in title block; ApprovedBy: Not shown in title block; CheckedBy: Not shown in title block; Author: Not shown in title block; CompanyName: Not shown in title block; Engineer: Not shown in title block; Organization: Not shown in title block; Address1: Not shown in title block; Address2: Not shown in title block; Address3: Not shown in title block; Address4: Not shown in title block; DocumentNumber: 6; Revision: Use project parameter SCH_Rev; SheetNumber: 6; SheetTotal: 7; PageSetup: Record=PageOptions¦CenterHorizontal=True¦CenterVertical=True¦PrintScale=1.00¦XCorrection=1.00¦YCorrection=1.00¦PrintKind=0¦BorderSize=5000000¦LeftOffset=0¦BottomOffset=0¦Orientation=2¦PaperLength=1000¦PaperWidth=1000¦Scale=100¦PaperSource=15¦PrintQuality=600¦MediaType=1¦DitherType=10¦PaperKind=Letter¦PrintScaleMode=1
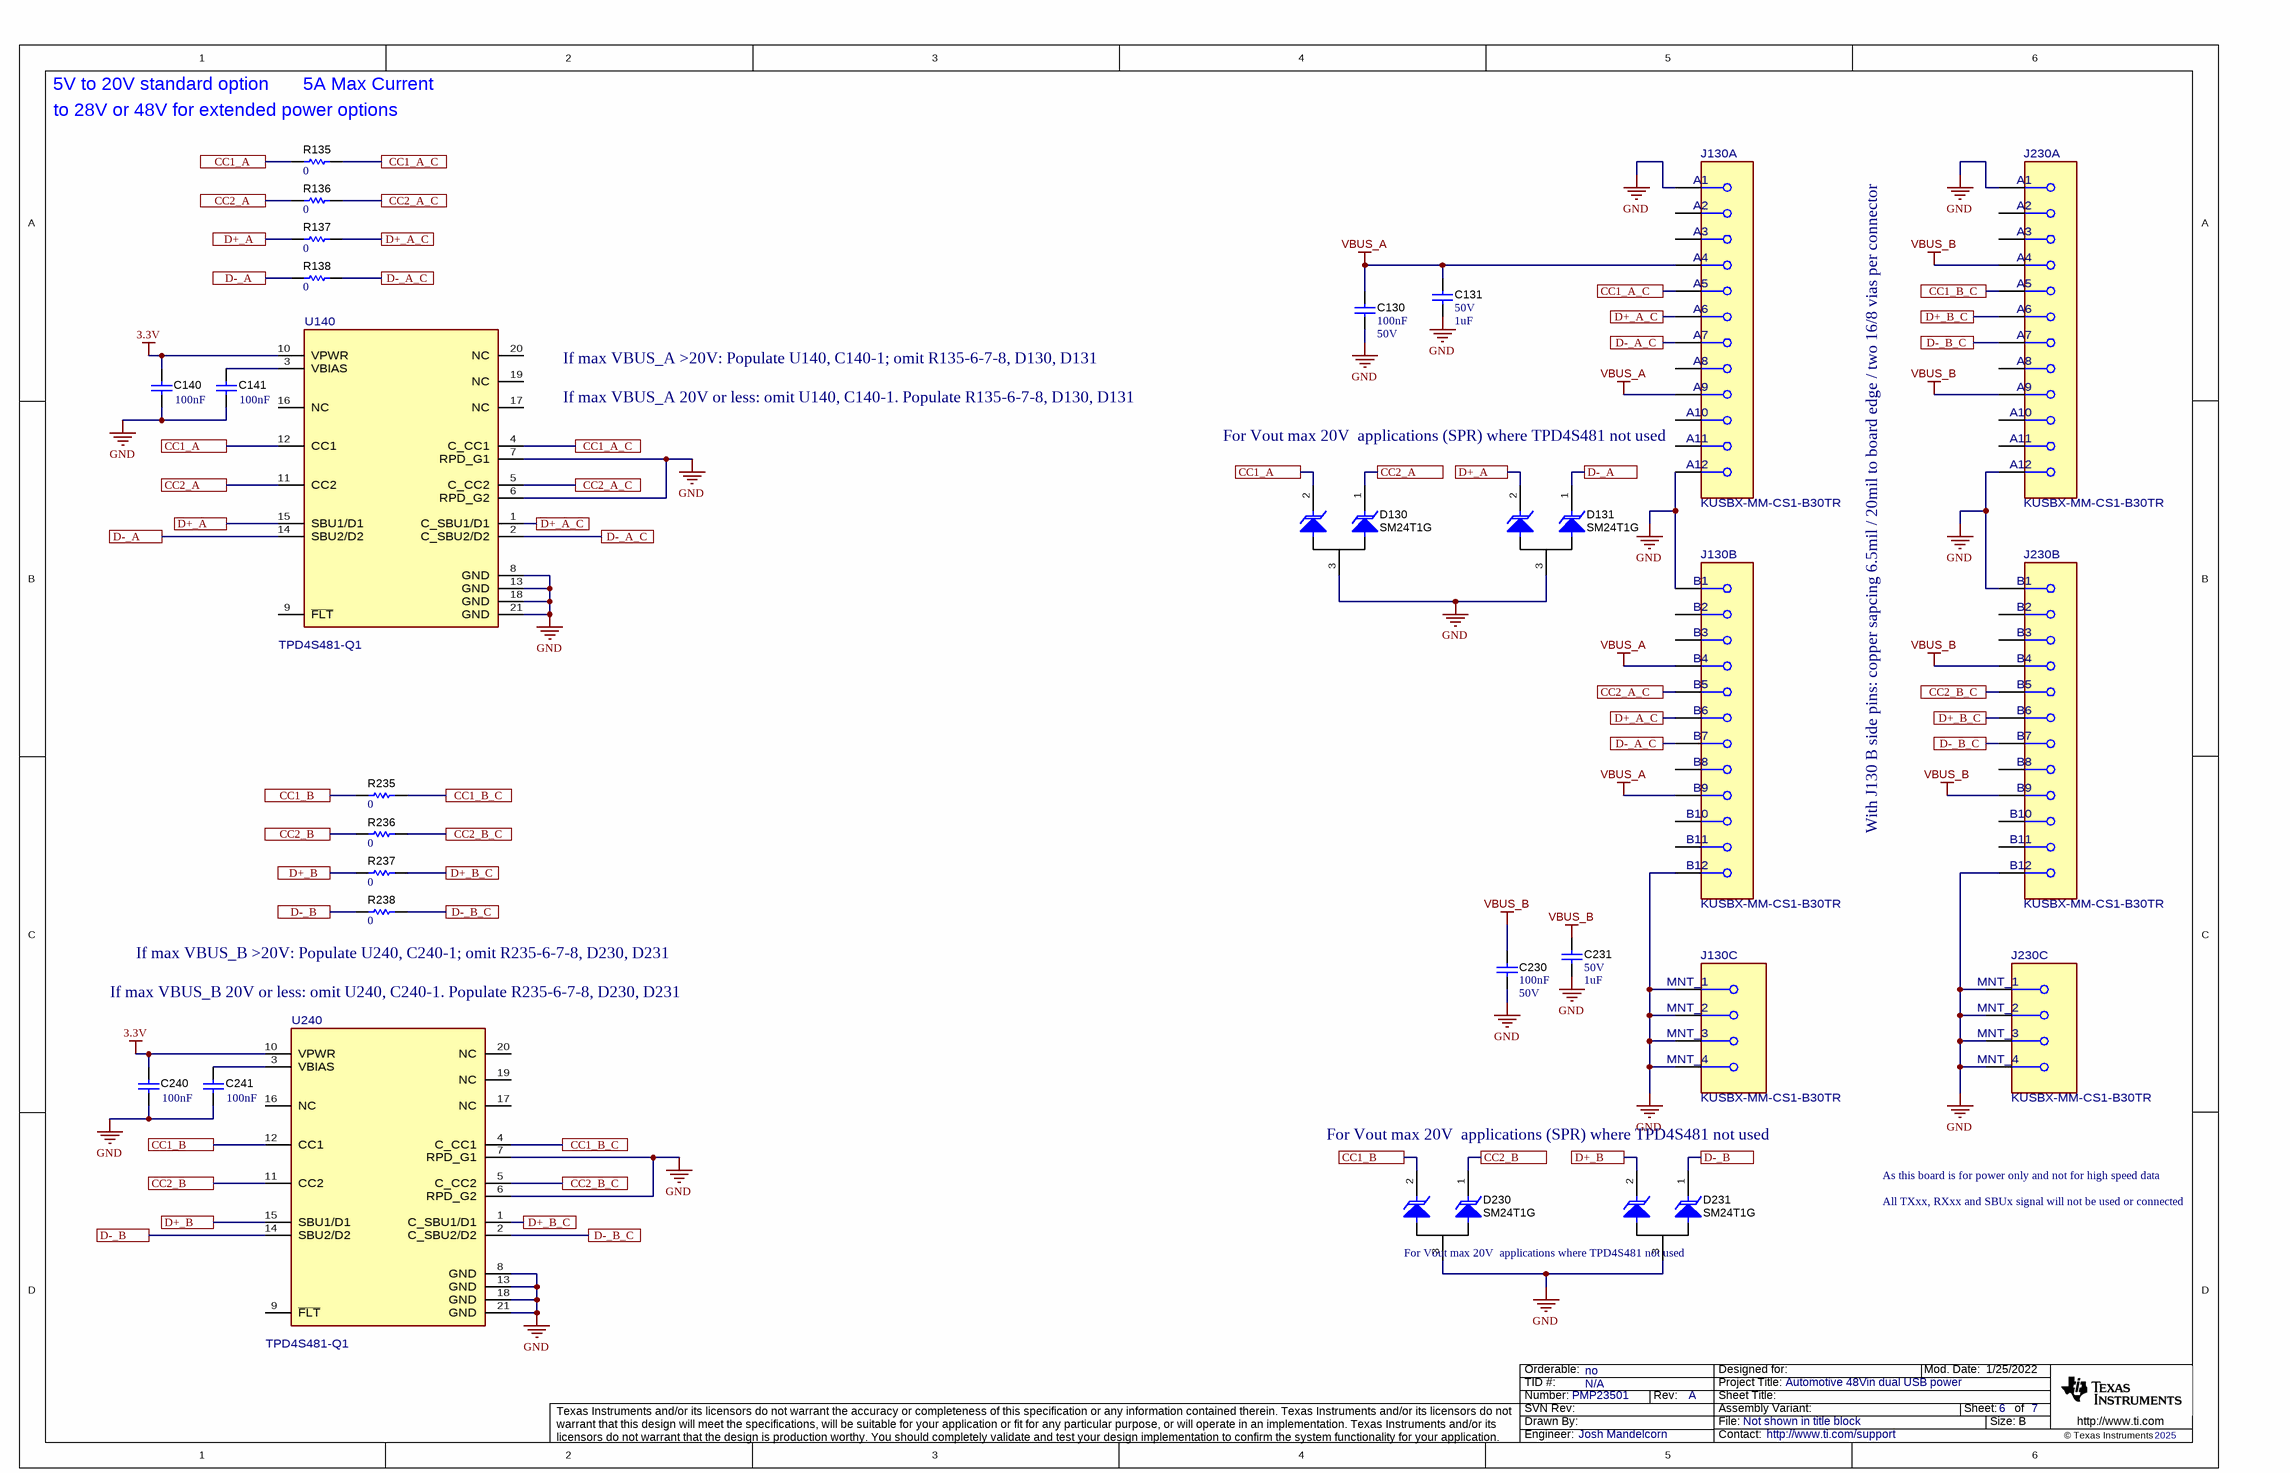
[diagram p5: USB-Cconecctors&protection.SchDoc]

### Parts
C130  Cap_F: 100nF  VDC_V: 50V  [0603]  (hidden comment: GCM188R71H104KA57D)
C131  VDC_V: 50V  ValueDisplayed: 1uF  [1206]  (hidden comment: GCM31MR71H105KA55L)
C140  Cap_F: 100nF  [0603]  (hidden comment: GCJ188R72A104KA01D)
C141  Cap_F: 100nF  [0603]  (hidden comment: GCJ188R72A104KA01D)
C230  Cap_F: 100nF  VDC_V: 50V  [0603]  (hidden comment: GCM188R71H104KA57D)
C231  VDC_V: 50V  ValueDisplayed: 1uF  [1206]  (hidden comment: GCM31MR71H105KA55L)
C240  Cap_F: 100nF  [0603]  (hidden comment: GCJ188R72A104KA01D)
C241  Cap_F: 100nF  [0603]  (hidden comment: GCJ188R72A104KA01D)
D130  SM24T1G  [SOT-23]
D131  SM24T1G  [SOT-23]
D230  SM24T1G  [SOT-23]
D231  SM24T1G  [SOT-23]
J130  KUSBX-MM-CS1-B30TR  [FP-KUSBX-MM-CS1-B30TR_CONN_USB-MFG]  (parts A,B,C of 3)
J230  KUSBX-MM-CS1-B30TR  [FP-KUSBX-MM-CS1-B30TR_CONN_USB-MFG]  (parts A,B,C of 3)
R135  value 0  [0603]  (hidden comment: RC0603JR-070RL)
R136  value 0  [0603]  (hidden comment: RC0603JR-070RL)
R137  value 0  [0603]  (hidden comment: RC0603JR-070RL)
R138  value 0  [0603]  (hidden comment: RC0603JR-070RL)
R235  value 0  [0603]  (hidden comment: RC0603JR-070RL)
R236  value 0  [0603]  (hidden comment: RC0603JR-070RL)
R237  value 0  [0603]  (hidden comment: RC0603JR-070RL)
R238  value 0  [0603]  (hidden comment: RC0603JR-070RL)
U140  TPD4S481-Q1  [RGR0020C-MFG]
U240  TPD4S481-Q1  [RGR0020C-MFG]

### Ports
CC1_A, CC1_A_C, CC1_B, CC1_B_C, CC2_A, CC2_A_C, CC2_B, CC2_B_C, D+_A, D+_A_C, D+_B, D+_B_C, D-_A, D-_A_C, D-_B, D-_B_C

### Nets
3.3V: C140.1 C240.1 U140.10(VPWR) U240.10(VPWR)
GND: C130.2 C131.2 C140.2 C141.2 C230.2 C231.2 C240.2 C241.2 D130.3(A) D131.3(A) D230.3(A) D231.3(A) J130.1(MNT_1) J130.2(MNT_2) J130.3(MNT_3) J130.4(MNT_4) J130.A1 J130.A12 J130.B1 J130.B12 J230.1(MNT_1) J230.2(MNT_2) J230.3(MNT_3) J230.4(MNT_4) J230.A1 J230.A12 J230.B1 J230.B12 U140.6(RPD_G2) U140.7(RPD_G1) U140.8(GND) U140.13(GND) U140.18(GND) U140.21(GND) U240.6(RPD_G2) U240.7(RPD_G1) U240.8(GND) U240.13(GND) U240.18(GND) U240.21(GND)
VBUS_A: C130.1 C131.1 J130.A4 J130.A9 J130.B4 J130.B9
VBUS_B: C230.1 C231.1 J230.A4 J230.A9 J230.B4 J230.B9
CC1_A: D130.2(C) R135.1 U140.12(CC1) ; port CC1_A
CC1_A_C: J130.A5 R135.2 U140.4(C_CC1) ; port CC1_A_C
CC1_B: D230.2(C) R235.1 U240.12(CC1) ; port CC1_B
CC1_B_C: J230.A5 R235.2 U240.4(C_CC1) ; port CC1_B_C
CC2_A: D130.1(C) R136.1 U140.11(CC2) ; port CC2_A
CC2_A_C: J130.B5 R136.2 U140.5(C_CC2) ; port CC2_A_C
CC2_B: D230.1(C) R236.1 U240.11(CC2) ; port CC2_B
CC2_B_C: J230.B5 R236.2 U240.5(C_CC2) ; port CC2_B_C
D+_A: D131.2(C) R137.1 U140.15(SBU1/D1) ; port D+_A
D+_A_C: J130.A6 J130.B6 R137.2 U140.1(C_SBU1/D1) ; port D+_A_C
D+_B: D231.2(C) R237.1 U240.15(SBU1/D1) ; port D+_B
D+_B_C: J230.A6 J230.B6 R237.2 U240.1(C_SBU1/D1) ; port D+_B_C
D-_A: D131.1(C) R138.1 U140.14(SBU2/D2) ; port D-_A
D-_A_C: J130.A7 J130.B7 R138.2 U140.2(C_SBU2/D2) ; port D-_A_C
D-_B: D231.1(C) R238.1 U240.14(SBU2/D2) ; port D-_B
D-_B_C: J230.A7 J230.B7 R238.2 U240.2(C_SBU2/D2) ; port D-_B_C
NetC141_1: C141.1 U140.3(VBIAS)
NetC241_1: C241.1 U240.3(VBIAS)

Not connected (* = marked no-connect by the designer): J130 A2 A3 A8 A10 A11 B2 B3 B8 B10 B11; J230 A2 A3 A8 A10 A11 B2 B3 B8 B10 B11; U140 9(~{FLT}) 16(NC) 17(NC) 19(NC) 20(NC); U240 9(~{FLT}) 16(NC) 17(NC) 19(NC) 20(NC)

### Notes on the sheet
- 5V to 20V standard option
- (near R135) to 28V or 48V for extended power options
- 5A Max Current
- If max VBUS_A >20V: Populate U140, C140-1; omit R135-6-7-8, D130, D131
- If max VBUS_A 20V or less: omit U140, C140-1. Populate R135-6-7-8, D130, D131
- (near J130) For Vout max 20V  applications (SPR) where TPD4S481 not used
- With J130 B side pins: copper sapcing 6.5mil / 20mil to board edge / two 16/8 vias per connector
- (near R238) If max VBUS_B >20V: Populate U240, C240-1; omit R235-6-7-8, D230, D231
- If max VBUS_B 20V or less: omit U240, C240-1. Populate R235-6-7-8, D230, D231
- For Vout max 20V  applications (SPR) where TPD4S481 not used
- As this board is for power only and not for high speed data
- All TXxx, RXxx and SBUx signal will not be used or connected
- For Vout max 20V  applications where TPD4S481 not used

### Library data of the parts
C130 C230 = CMP-0007144-4: as C4 on sheet InputPower&Protection
C131 C231 = CMP-0008818-2: CAP, CERM, 1 uF, 50 V, +/- 10%, X7R, AEC-Q200 Grade 1, 1206; Manufacturer: MuRata; TaMin_C: -55°C; Polarized: N; SizeAreaWB_mm2: 10.92; Value1: Unknown; U/M: EA; Value: 1uF; TaMax_C: 125°C; SizeZ_mm: 1.35; SizeX_mm: 3.2; SizeY_mm: 1.6; SizeArea_mm2: 5.12; AEC Qualified: Y; Cap_F: 1µF; AEC Grade: 1; AEC Category: Q200
C140 C141 C240 C241 = CMP-0064935-4: as C10 on sheet EPR_Controller_Dual
D130 D131 D230 D231 = CMP-0005927-3: Diode, TVS, Uni, 5 V, SOT-23; Manufacturer: ON Semiconductor; VRWM: 5V; Ppk: 300W; Value: 5V; SizeY_mm: 3; SizeX_mm: 2.5; AEC Category: Q101; RJA_CperW: 556; SizeZ_mm: 1.1; SizeAreaWB_mm2: 14; SizeArea_mm2: 7.5
J130 J230 = CMP-0124069-1: USB Connectors USB TYPE C SOCKET MIDMOUNT BLK 30u T/R; Manufacturer: Kycon; ContactFinish: Gold,Nickel; Shrouded: true; Voltage_V: 30V; AEC Qualified: No; Conn Orientation: Horizontal; DUT-Pitch_mm: 0.5mm; Is Female: yes; SizeZ_mm: 2.43mm; Usb Standard: USB 3.1
R135-R138 R235-R238 = CMP-0025885-5: as R106 on sheet DCDC_A
U140 U240 = CMP-0035132-1: USB Type-C® 48V EPR Port Protector: Short-to-VBUS Overvoltage and IEC ESD Protection; Manufacturer: Texas Instruments; PartNumber: TPD4S481QRGRRQ1; SizeZ_mm: 1mm; AEC Qualified: Yes; AEC Grade: Grade 1; Direction: Bidirectional; Number Of Channels: 4; Operating Supply Voltage: 3.3V; Standoff Height: 0mm; TJmax_C: +125°C

## Sheet PMP23501_Hardware.SchDoc
size 431 x 279 mm; Date: Not shown in title block; ApprovedBy: Not shown in title block; CheckedBy: Not shown in title block; Author: Not shown in title block; CompanyName: Not shown in title block; Engineer: Not shown in title block; Organization: Not shown in title block; Address1: Not shown in title block; Address2: Not shown in title block; Address3: Not shown in title block; Address4: Not shown in title block; DocumentNumber: 7; Revision: Use project parameter SCH_Rev; SheetNumber: 7; SheetTotal: 7; PageSetup: Record=PageOptions¦CenterHorizontal=True¦CenterVertical=True¦PrintScale=1.00¦XCorrection=1.00¦YCorrection=1.00¦PrintKind=0¦BorderSize=5000000¦LeftOffset=0¦BottomOffset=0¦Orientation=2¦PaperLength=1000¦PaperWidth=1000¦Scale=100¦PaperSource=15¦PrintQuality=600¦MediaType=1¦DitherType=10¦PaperKind=Letter¦PrintScaleMode=1
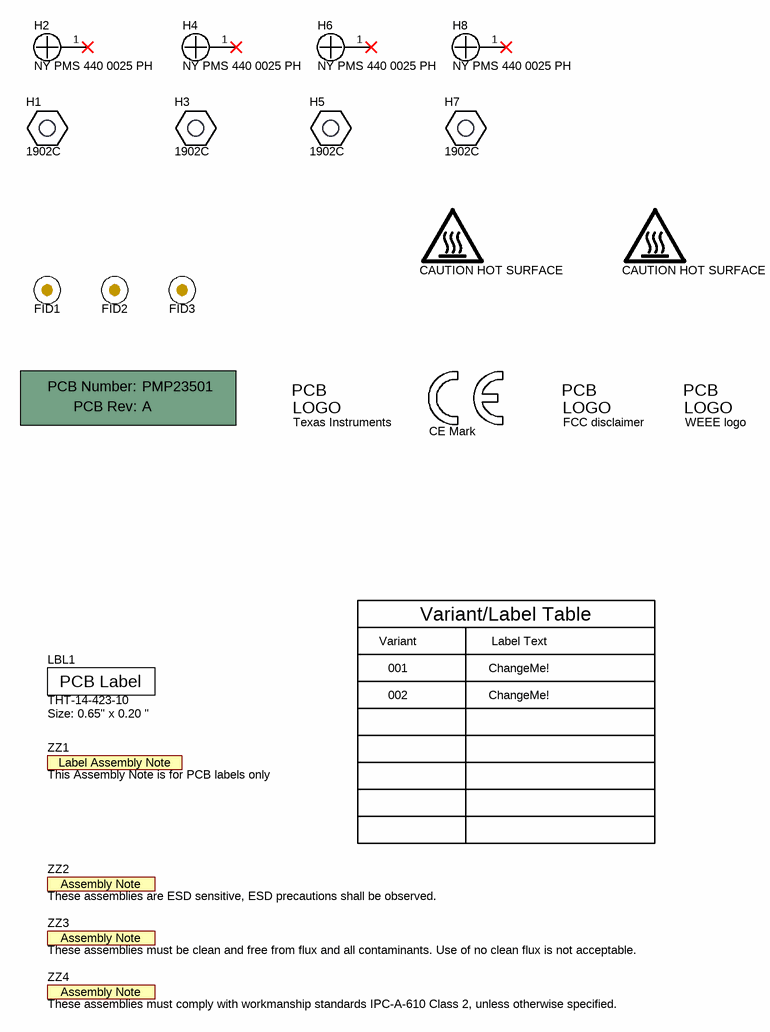
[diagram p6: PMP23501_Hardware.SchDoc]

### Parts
!PCB1  Printed Circuit Board  (value not drawn)  (mechanical)
FID1  Fiducial  [Fiducial10-20]  (value not drawn)
FID2  Fiducial  [Fiducial10-20]  (value not drawn)
FID3  Fiducial  [Fiducial10-20]  (value not drawn)
H1  1902C  [Keystone_1902C]
H2  NY PMS 440 0025 PH  [NY PMS 440 0025 PH]
H3  1902C  [Keystone_1902C]
H4  NY PMS 440 0025 PH  [NY PMS 440 0025 PH]
H5  1902C  [Keystone_1902C]
H6  NY PMS 440 0025 PH  [NY PMS 440 0025 PH]
H7  1902C  [Keystone_1902C]
H8  NY PMS 440 0025 PH  [NY PMS 440 0025 PH]
LBL1  THT-14-423-10  Note: Size: 0.65" x 0.20 "  [Label_650x200]
Logo1  Texas Instruments  [TI_Stacked_Overlay_Small]  (no BOM)
Logo2  CE Mark  [CE_Mark_5mm]  (no BOM)
Logo3  FCC disclaimer  [FCC_disclaimer]  (no BOM)
Logo4  WEEE logo  [WEEE_Minimum]  (no BOM)
Logo5  CAUTION HOT SURFACE  [IEC_HotSurface_Small]  (no BOM)
Logo6  CAUTION HOT SURFACE  [IEC_HotSurface_Small]  (no BOM)
ZZ1  This Assembly Note is for PCB labels only  [AssemblyNoteLabel]  (no BOM)
ZZ2  These assemblies are ESD sensitive, ESD precautions shall be observed.  [AssemblyNote]  (no BOM)
ZZ3  These assemblies must be clean and free from flux and all contaminants. Use of no clean flux is not acceptable.  [AssemblyNote]  (no BOM)
ZZ4  These assemblies must comply with workmanship standards IPC-A-610 Class 2, unless otherwise specified.  [AssemblyNote]  (no BOM)

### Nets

Not connected (* = marked no-connect by the designer): H2 1*; H4 1*; H6 1*; H8 1*

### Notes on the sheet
- Variant
- Variant/Label Table
- Label Text
- 001
- 002
- ChangeMe!

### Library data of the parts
!PCB1 = CMP-0003618-2: Manufacturer: Any; PartNumber: PMP23501
FID1-FID3 = CMP-0077181-1: Fiducial mark.  There is nothing to buy or mount.
H1 H3 H5 H7 = CMP-0003610-1: Standoff, Hex, 0.5"L #4-40 Nylon; Manufacturer: Keystone; CompType: Hardware
H2 H4 H6 H8 = CMP-0003617-1: Machine Screw, Round, #4-40 x 1/4, Nylon, Philips panhead; Manufacturer: B&F Fastener Supply; CompType: Hardware
LBL1 = CMP-0003625-1: Thermal Transfer Printable Labels, 0.650" W x 0.200" H - 10,000 per roll; Manufacturer: Brady; CompType: Label
Logo1 = CMP-0074838-1: Texas Instrument Corporate Signature; SymbolCreator: a0412235; Lib Reference: TI_Logo; Library Reference: Logo
Logo2 = CMP-0074844-1: SymbolCreator: a0412235
Logo3 = CMP-0074847-1: FCC_disclaimer; Library Reference: Logo
Logo4 = CMP-0074769-1
Logo5 Logo6 = CMP-0074837-2: IEC 61010-1 Hot Surface Warning; Manufacturer: Texas Instruments; CompType: IC; AEC Category: Q200; SymbolCreator: a0412235
ZZ1 = CMP-0003616-3
ZZ2 = CMP-0077236-1
ZZ3 = CMP-0077237-1
ZZ4 = CMP-0077238-1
